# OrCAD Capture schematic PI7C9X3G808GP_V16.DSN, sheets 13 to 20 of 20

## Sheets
13 14_SIGNAL SWITCH: size Custom; note: 14_SIGNAL SWITCH
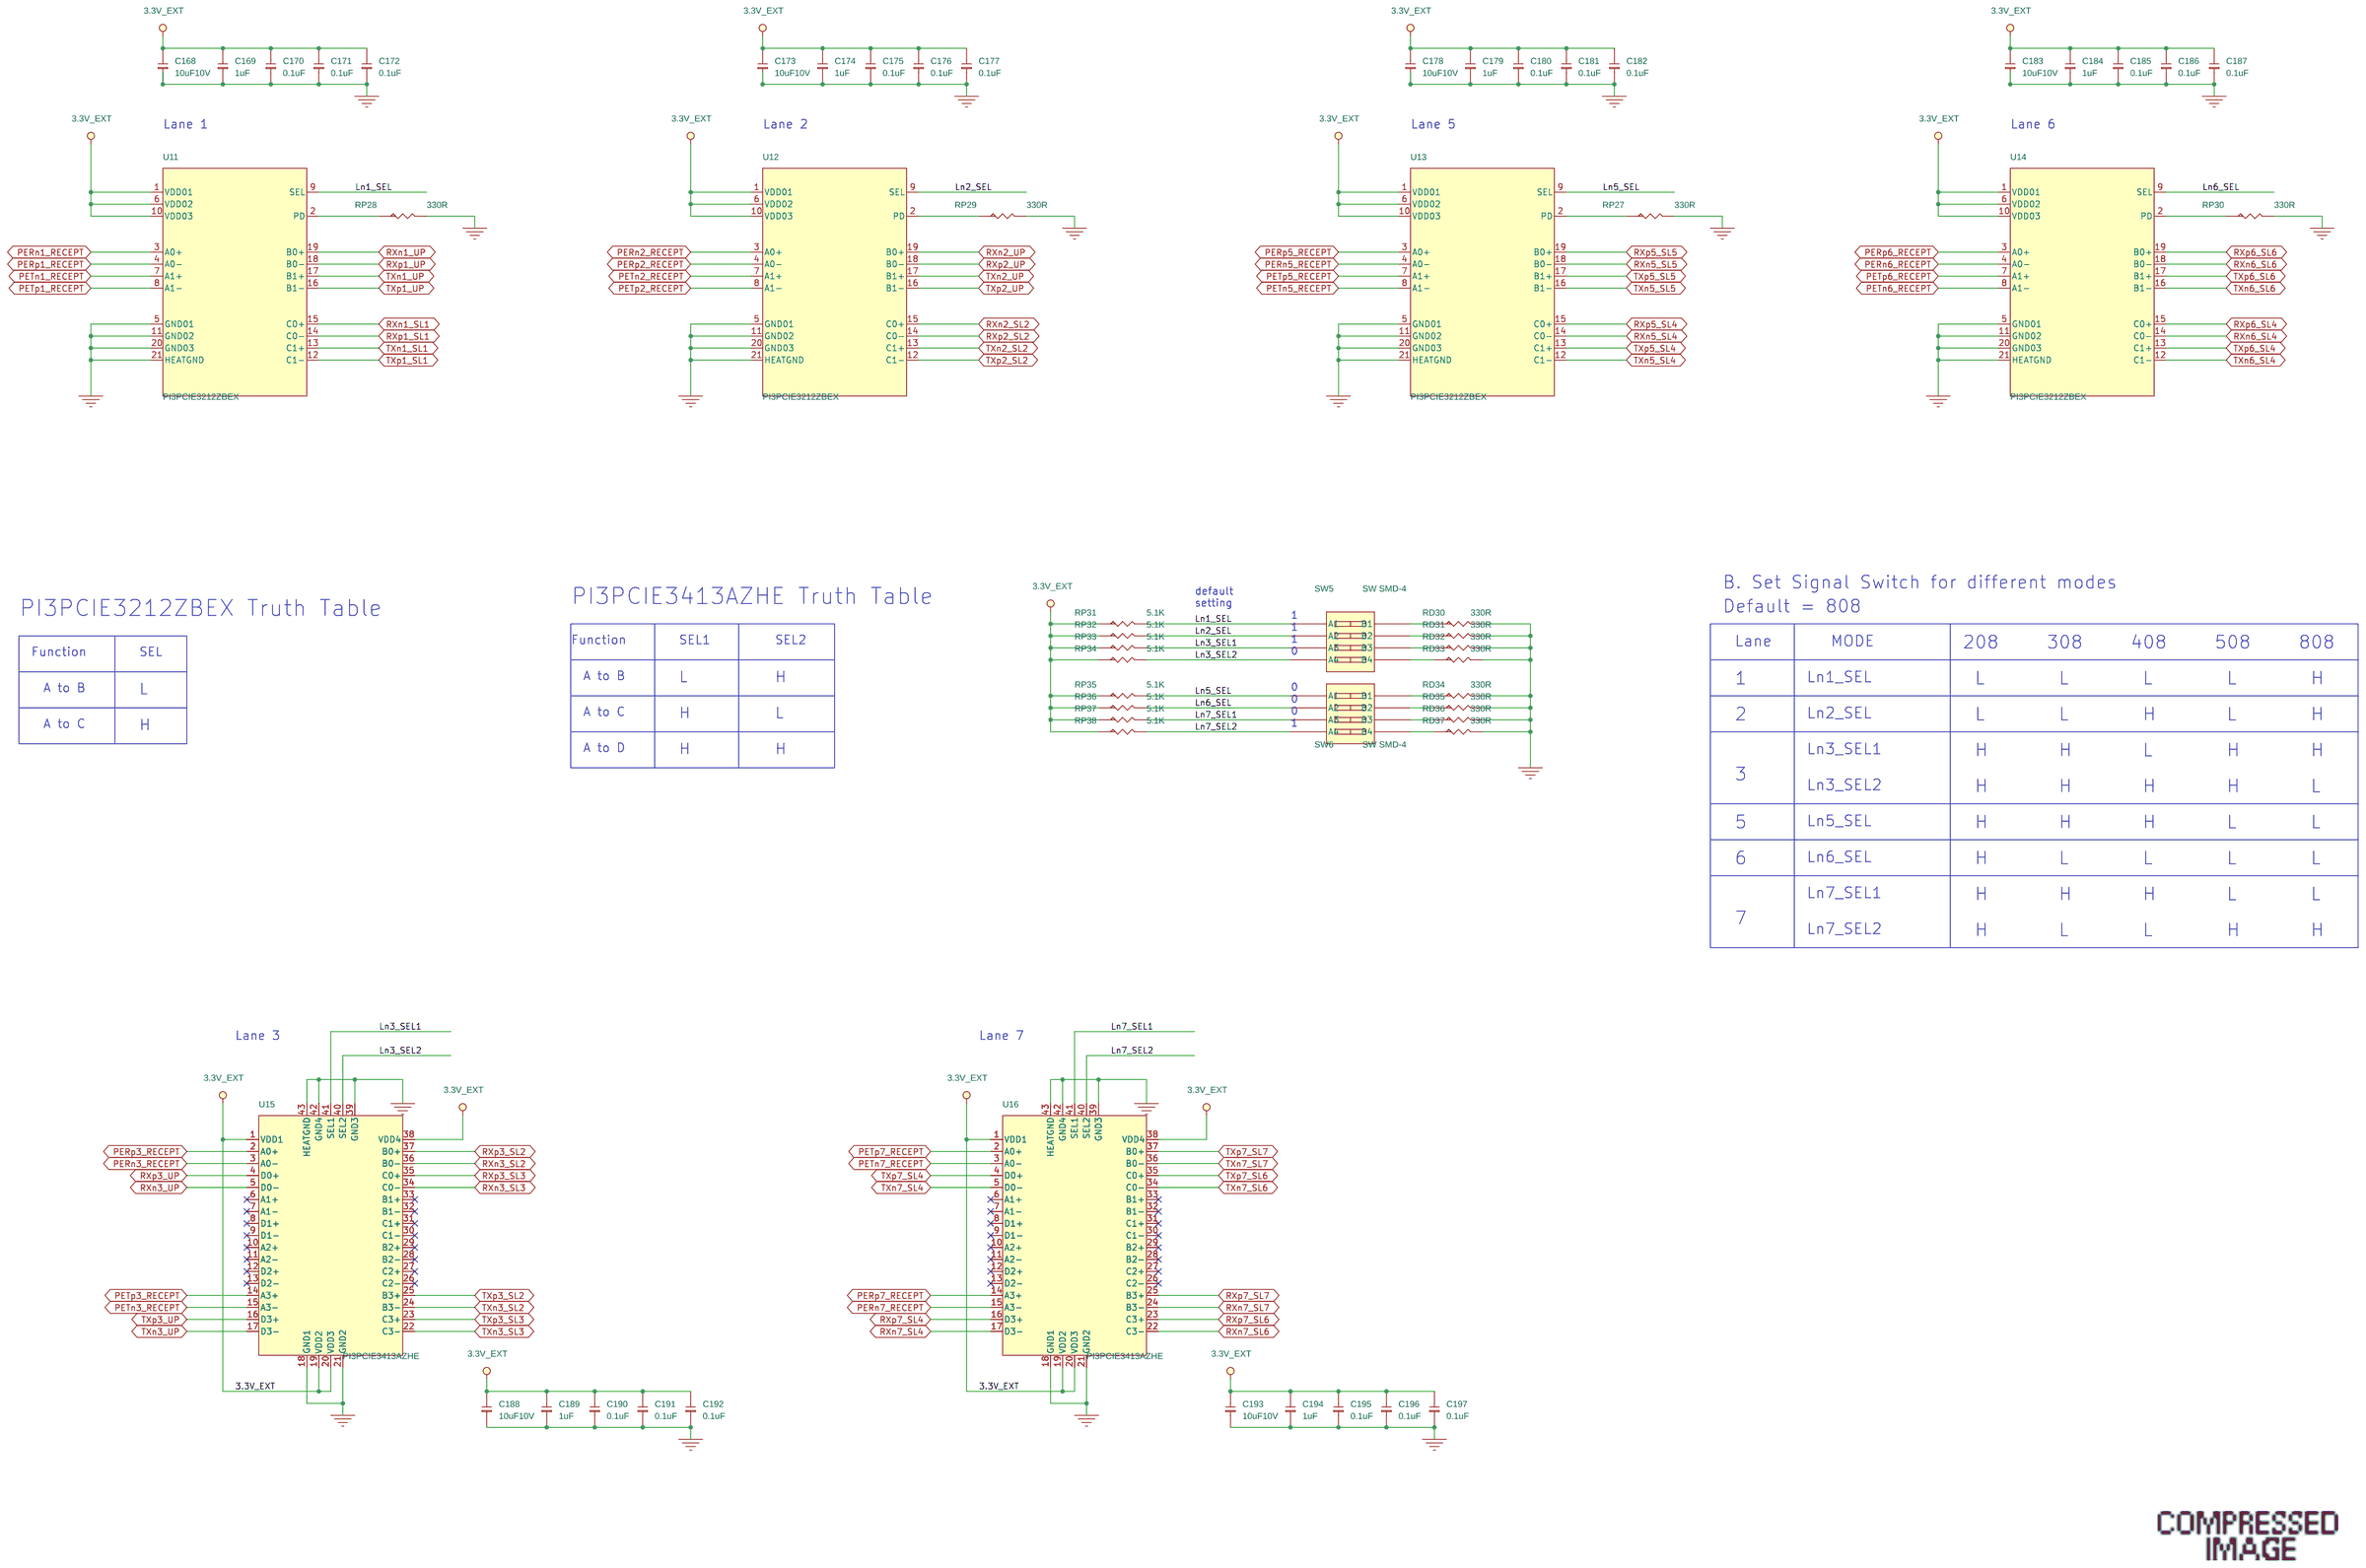
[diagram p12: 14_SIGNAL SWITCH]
14 15_CLOCK BUFFER: size B; note: 15_CLOCK BUFFER
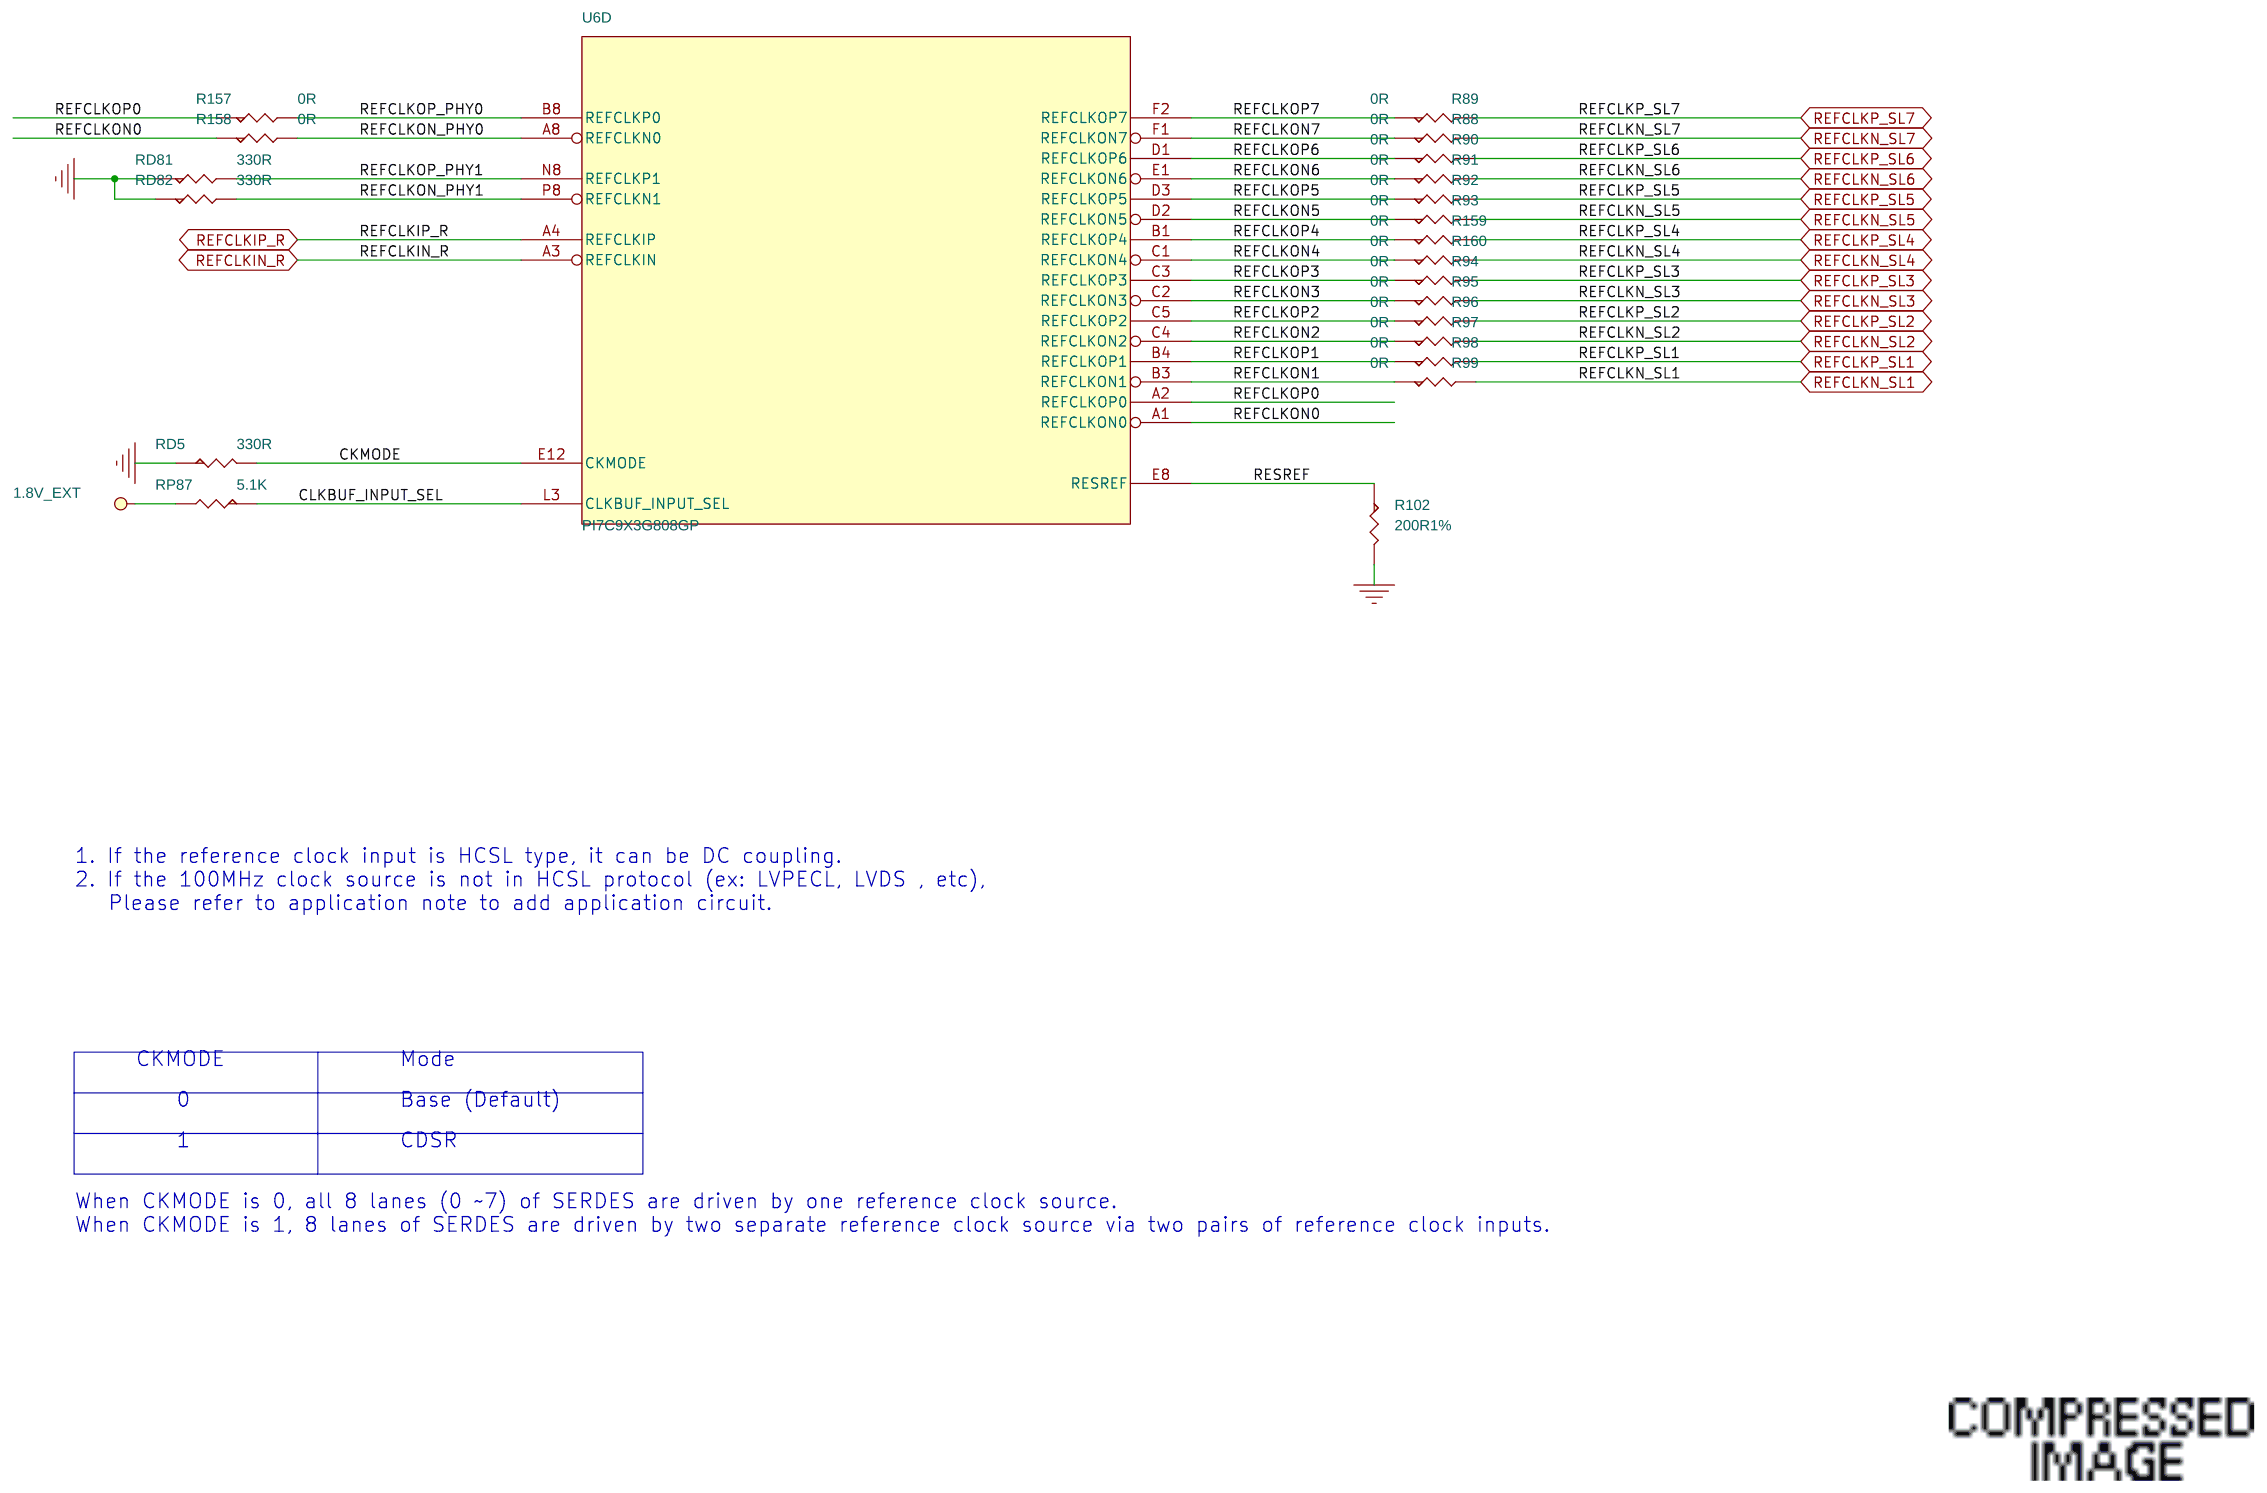
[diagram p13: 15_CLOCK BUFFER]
15 17_PERST SIGNAL: size B; note: 17_PERST SIGNAL & PORT LED
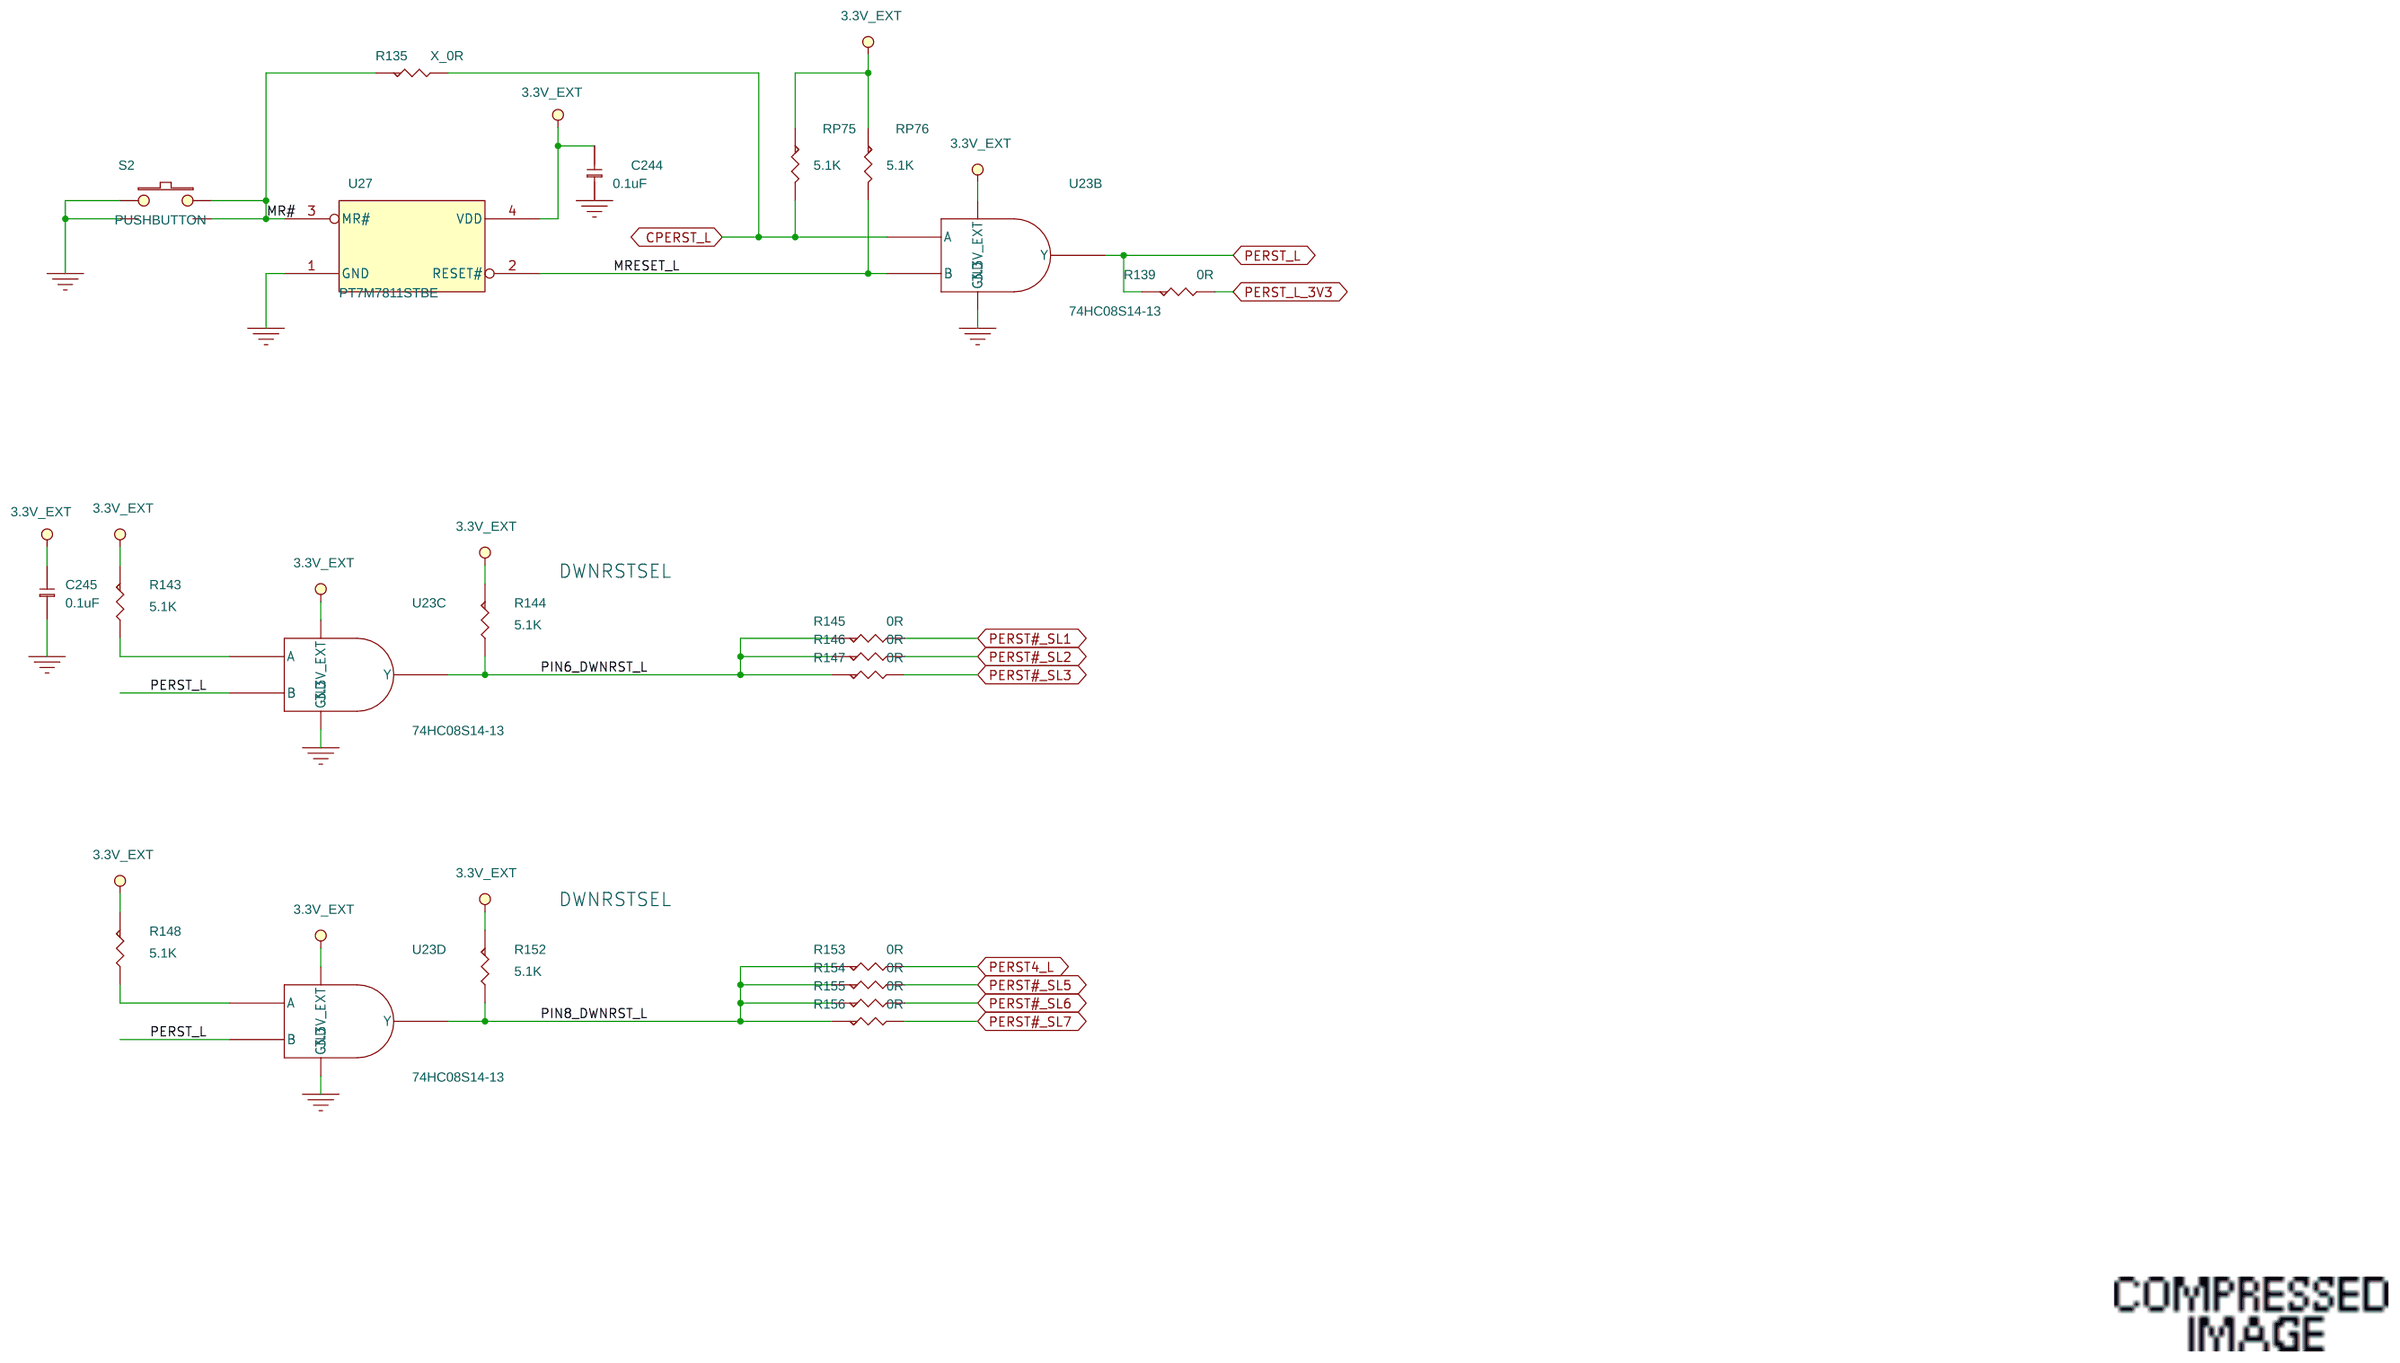
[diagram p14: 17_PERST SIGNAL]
16 18_GPIO: size B; note: 18_GPIO
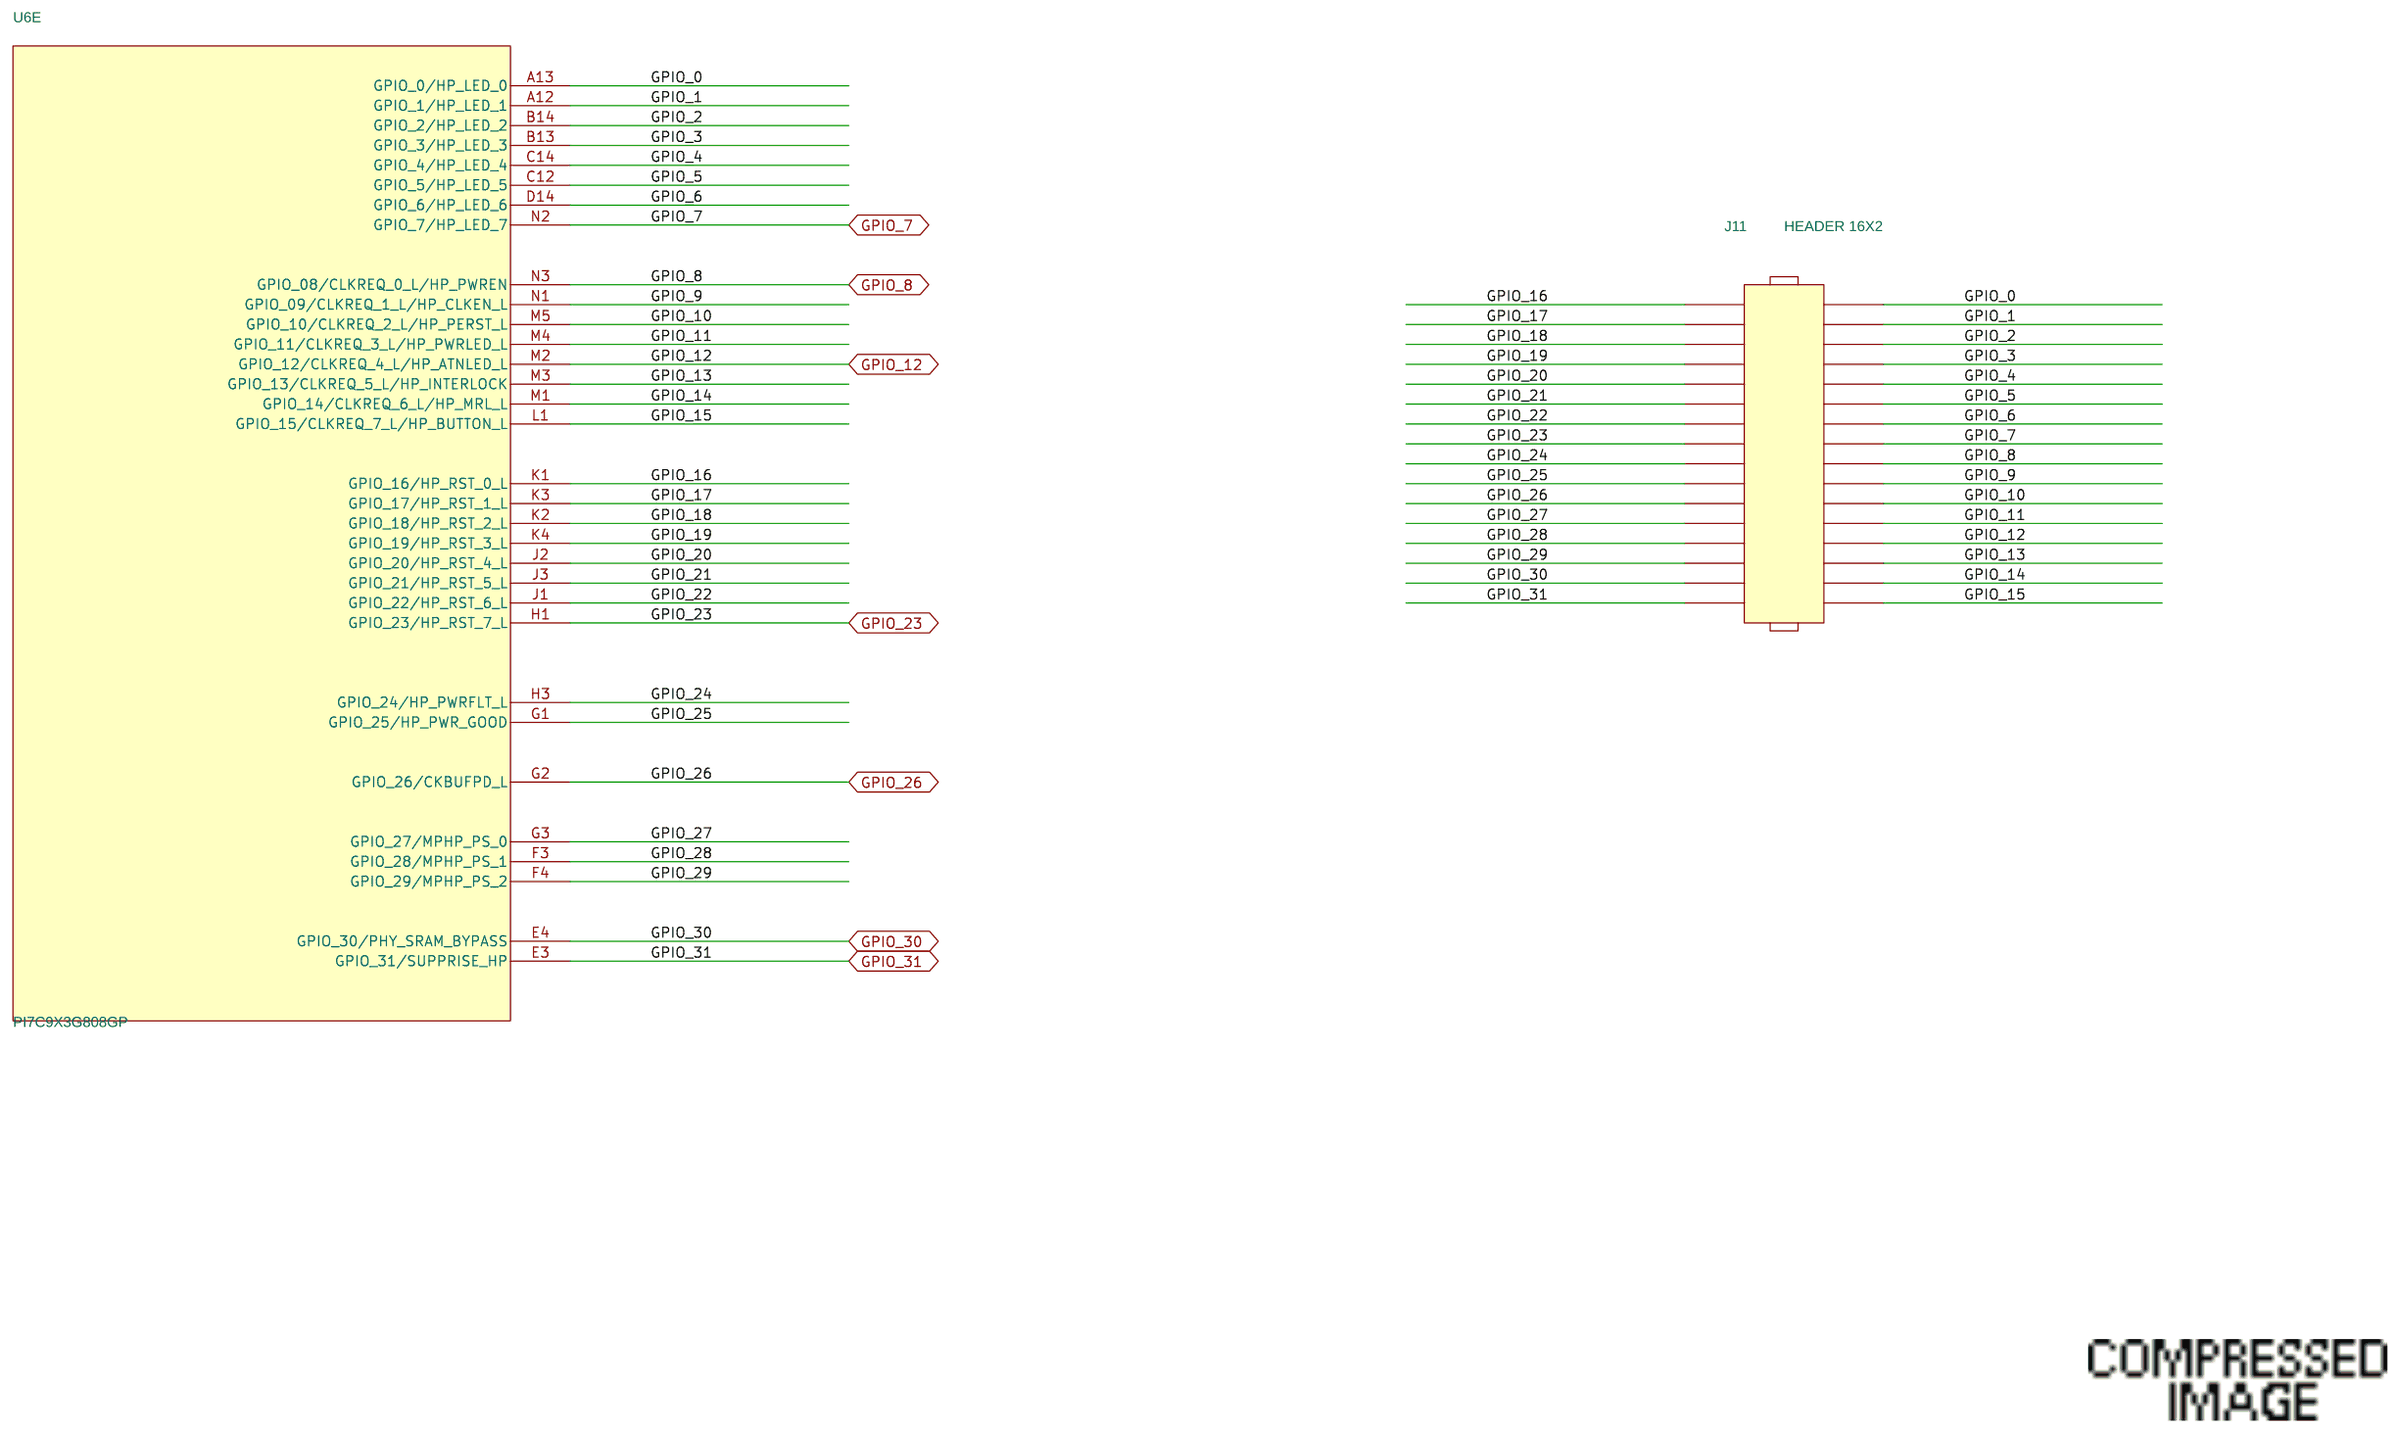
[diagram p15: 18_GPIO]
17 19_REVISION HISTORY: note: 19_REVISION HISTORY
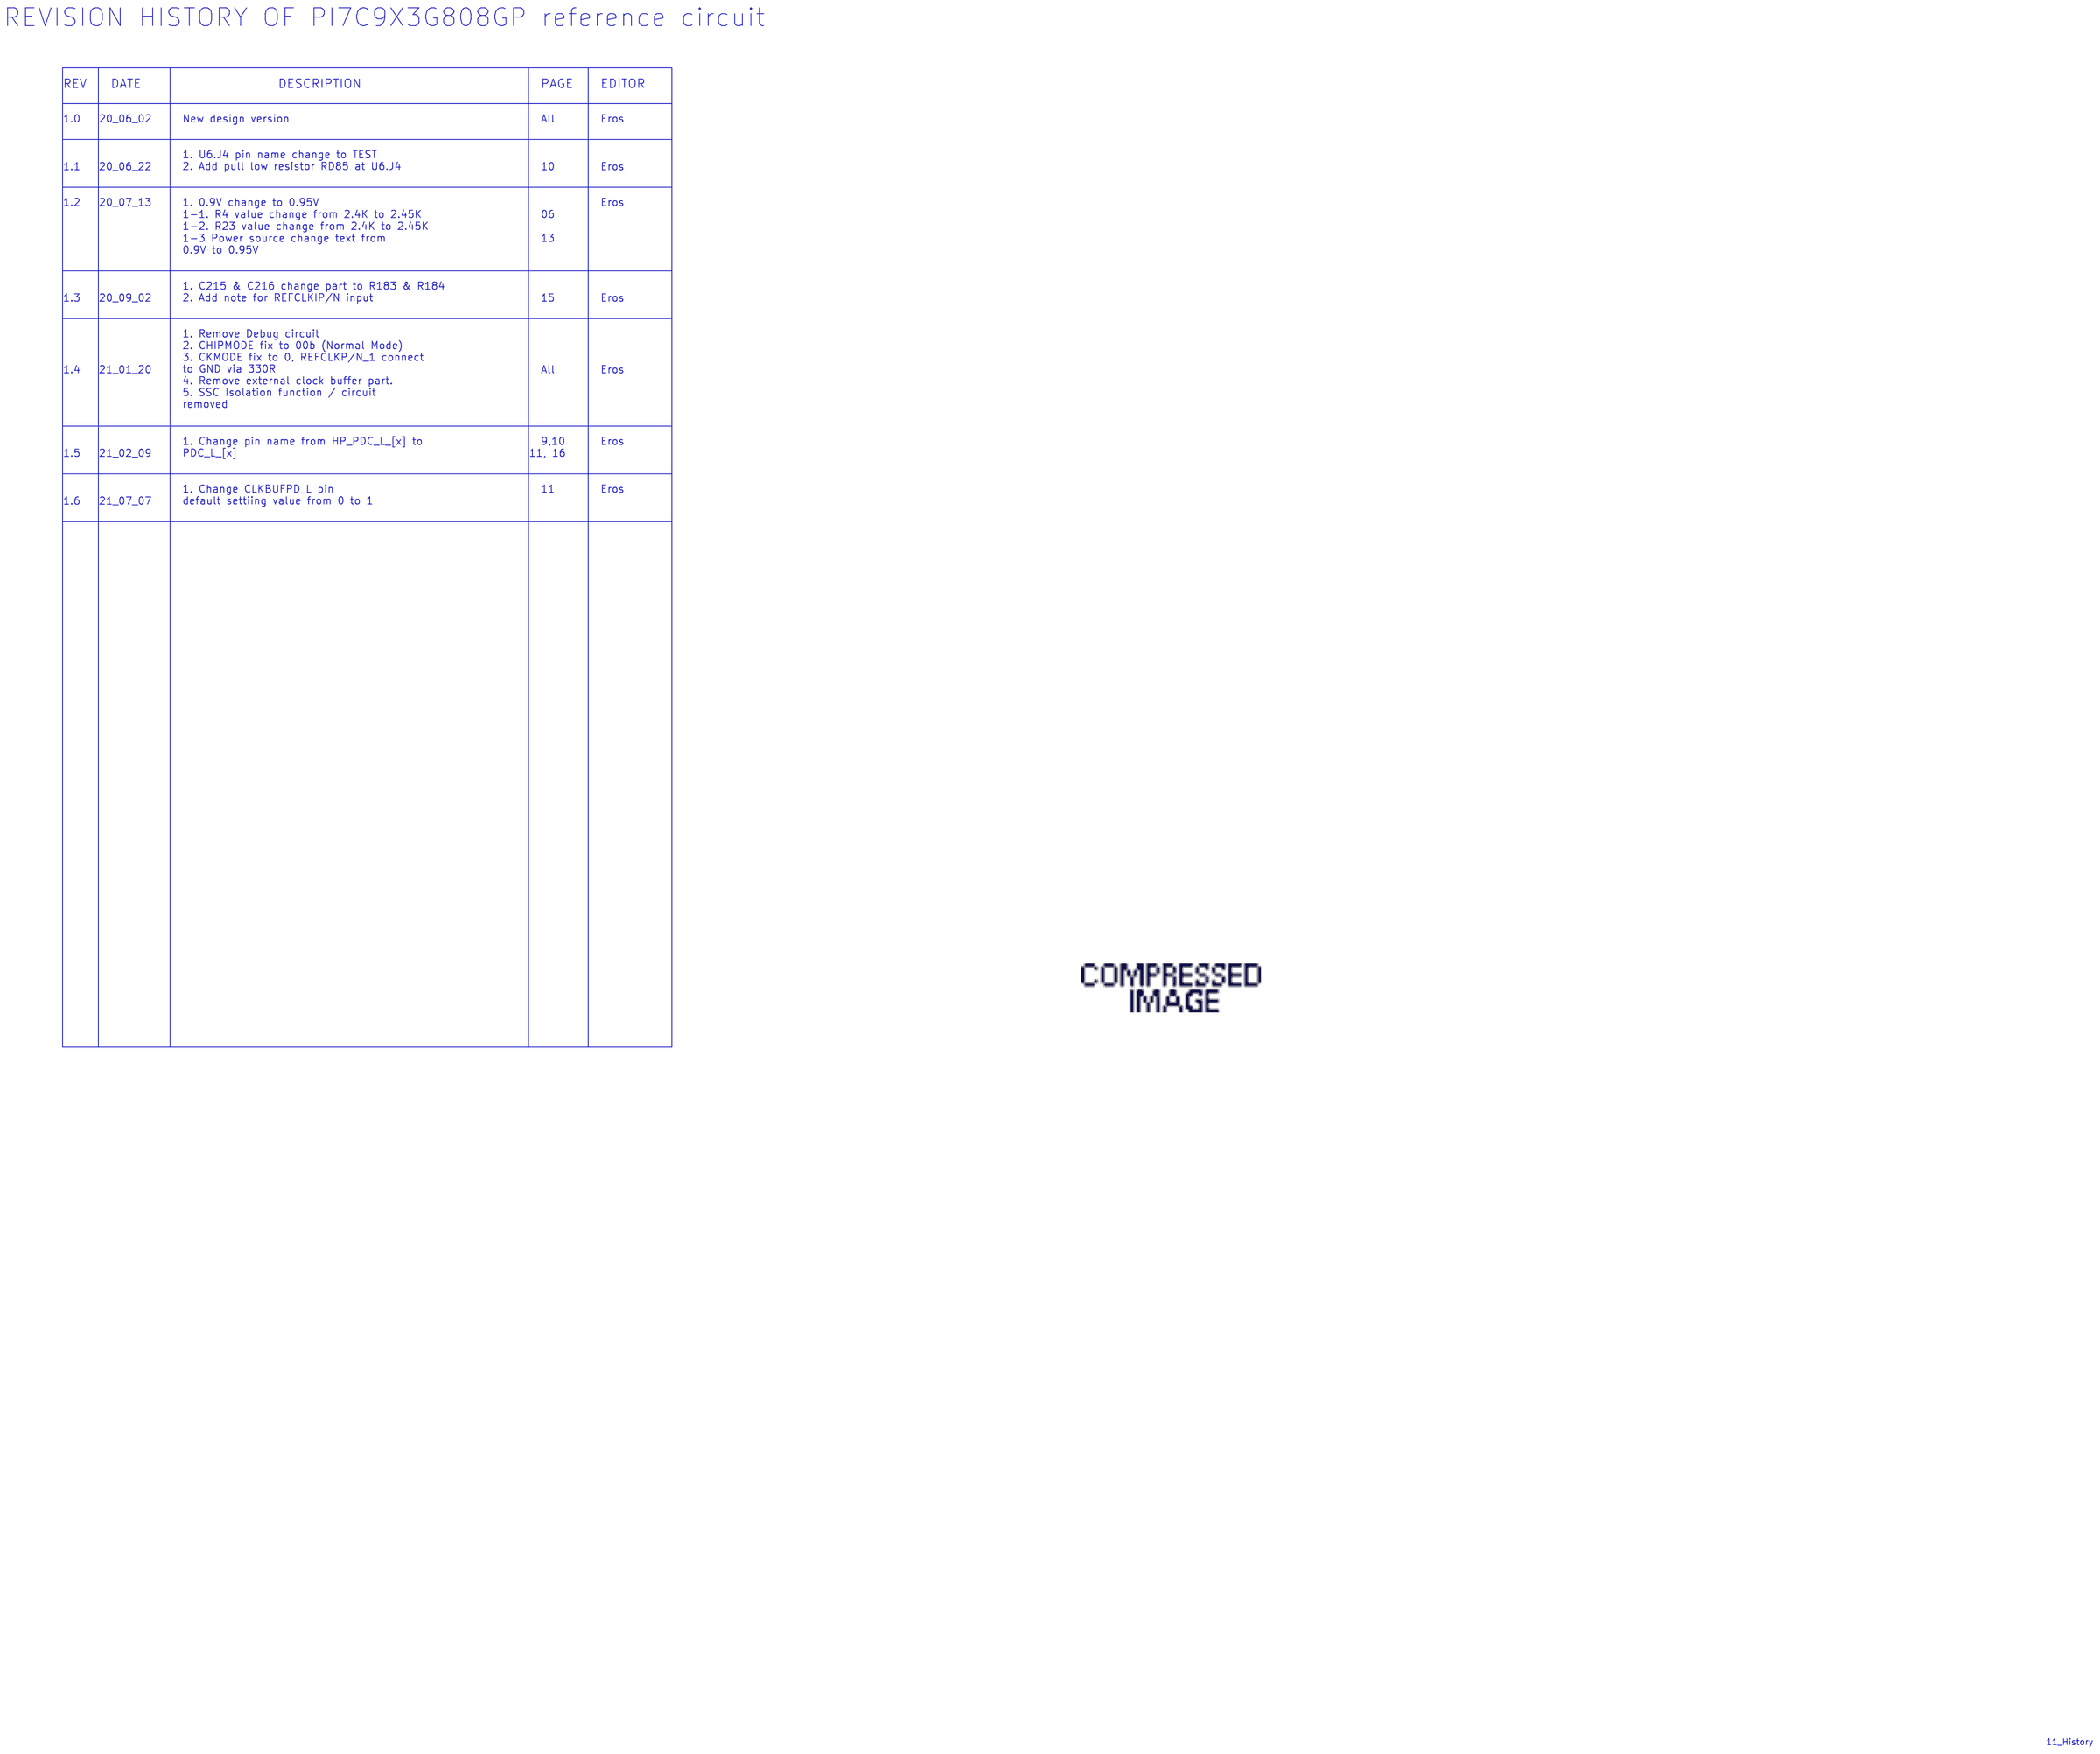
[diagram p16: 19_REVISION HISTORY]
18 20_DISCLAIMER: note: 20_DISCLAIMER
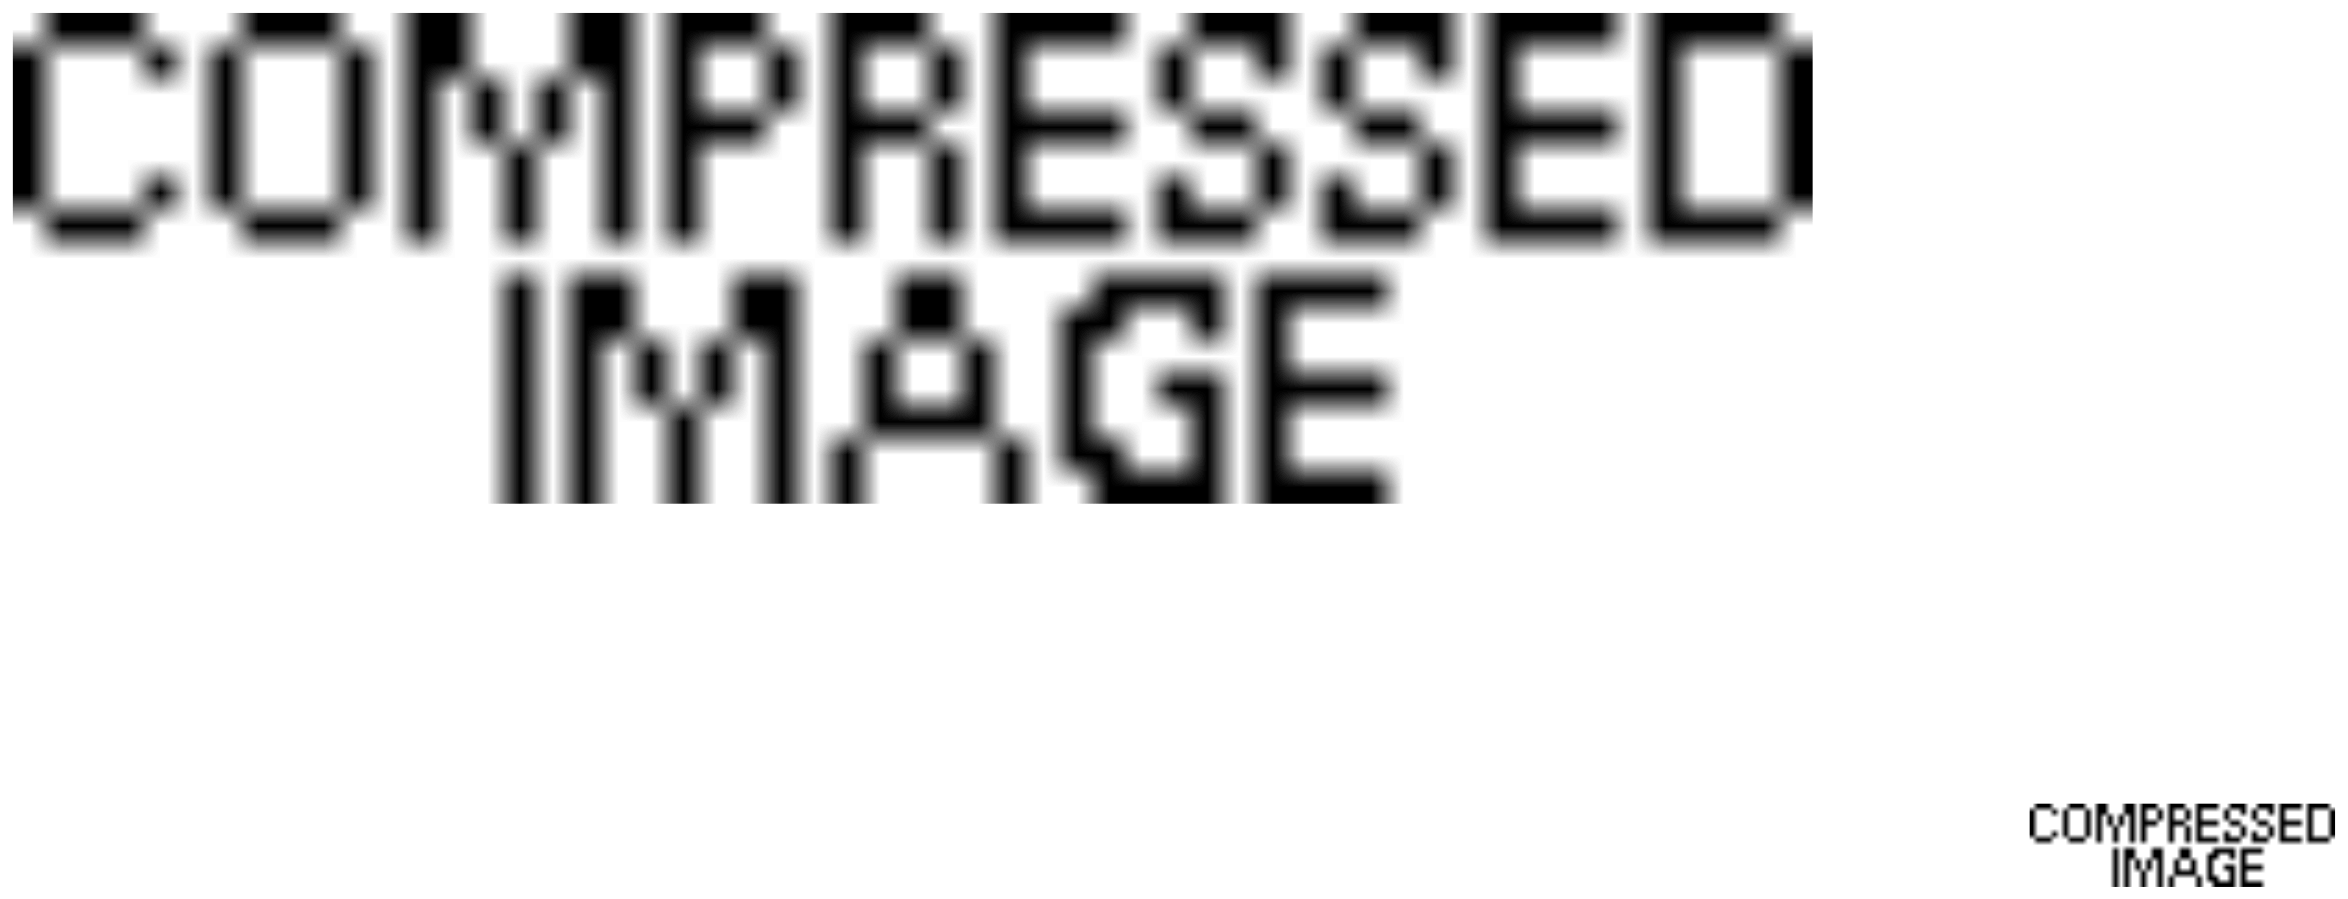
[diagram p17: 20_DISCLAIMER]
19 16_SHP / PARTIAL HP / PM L1.1: size Custom; note: 16_SHP / PARTIAL HP / PM L1.1
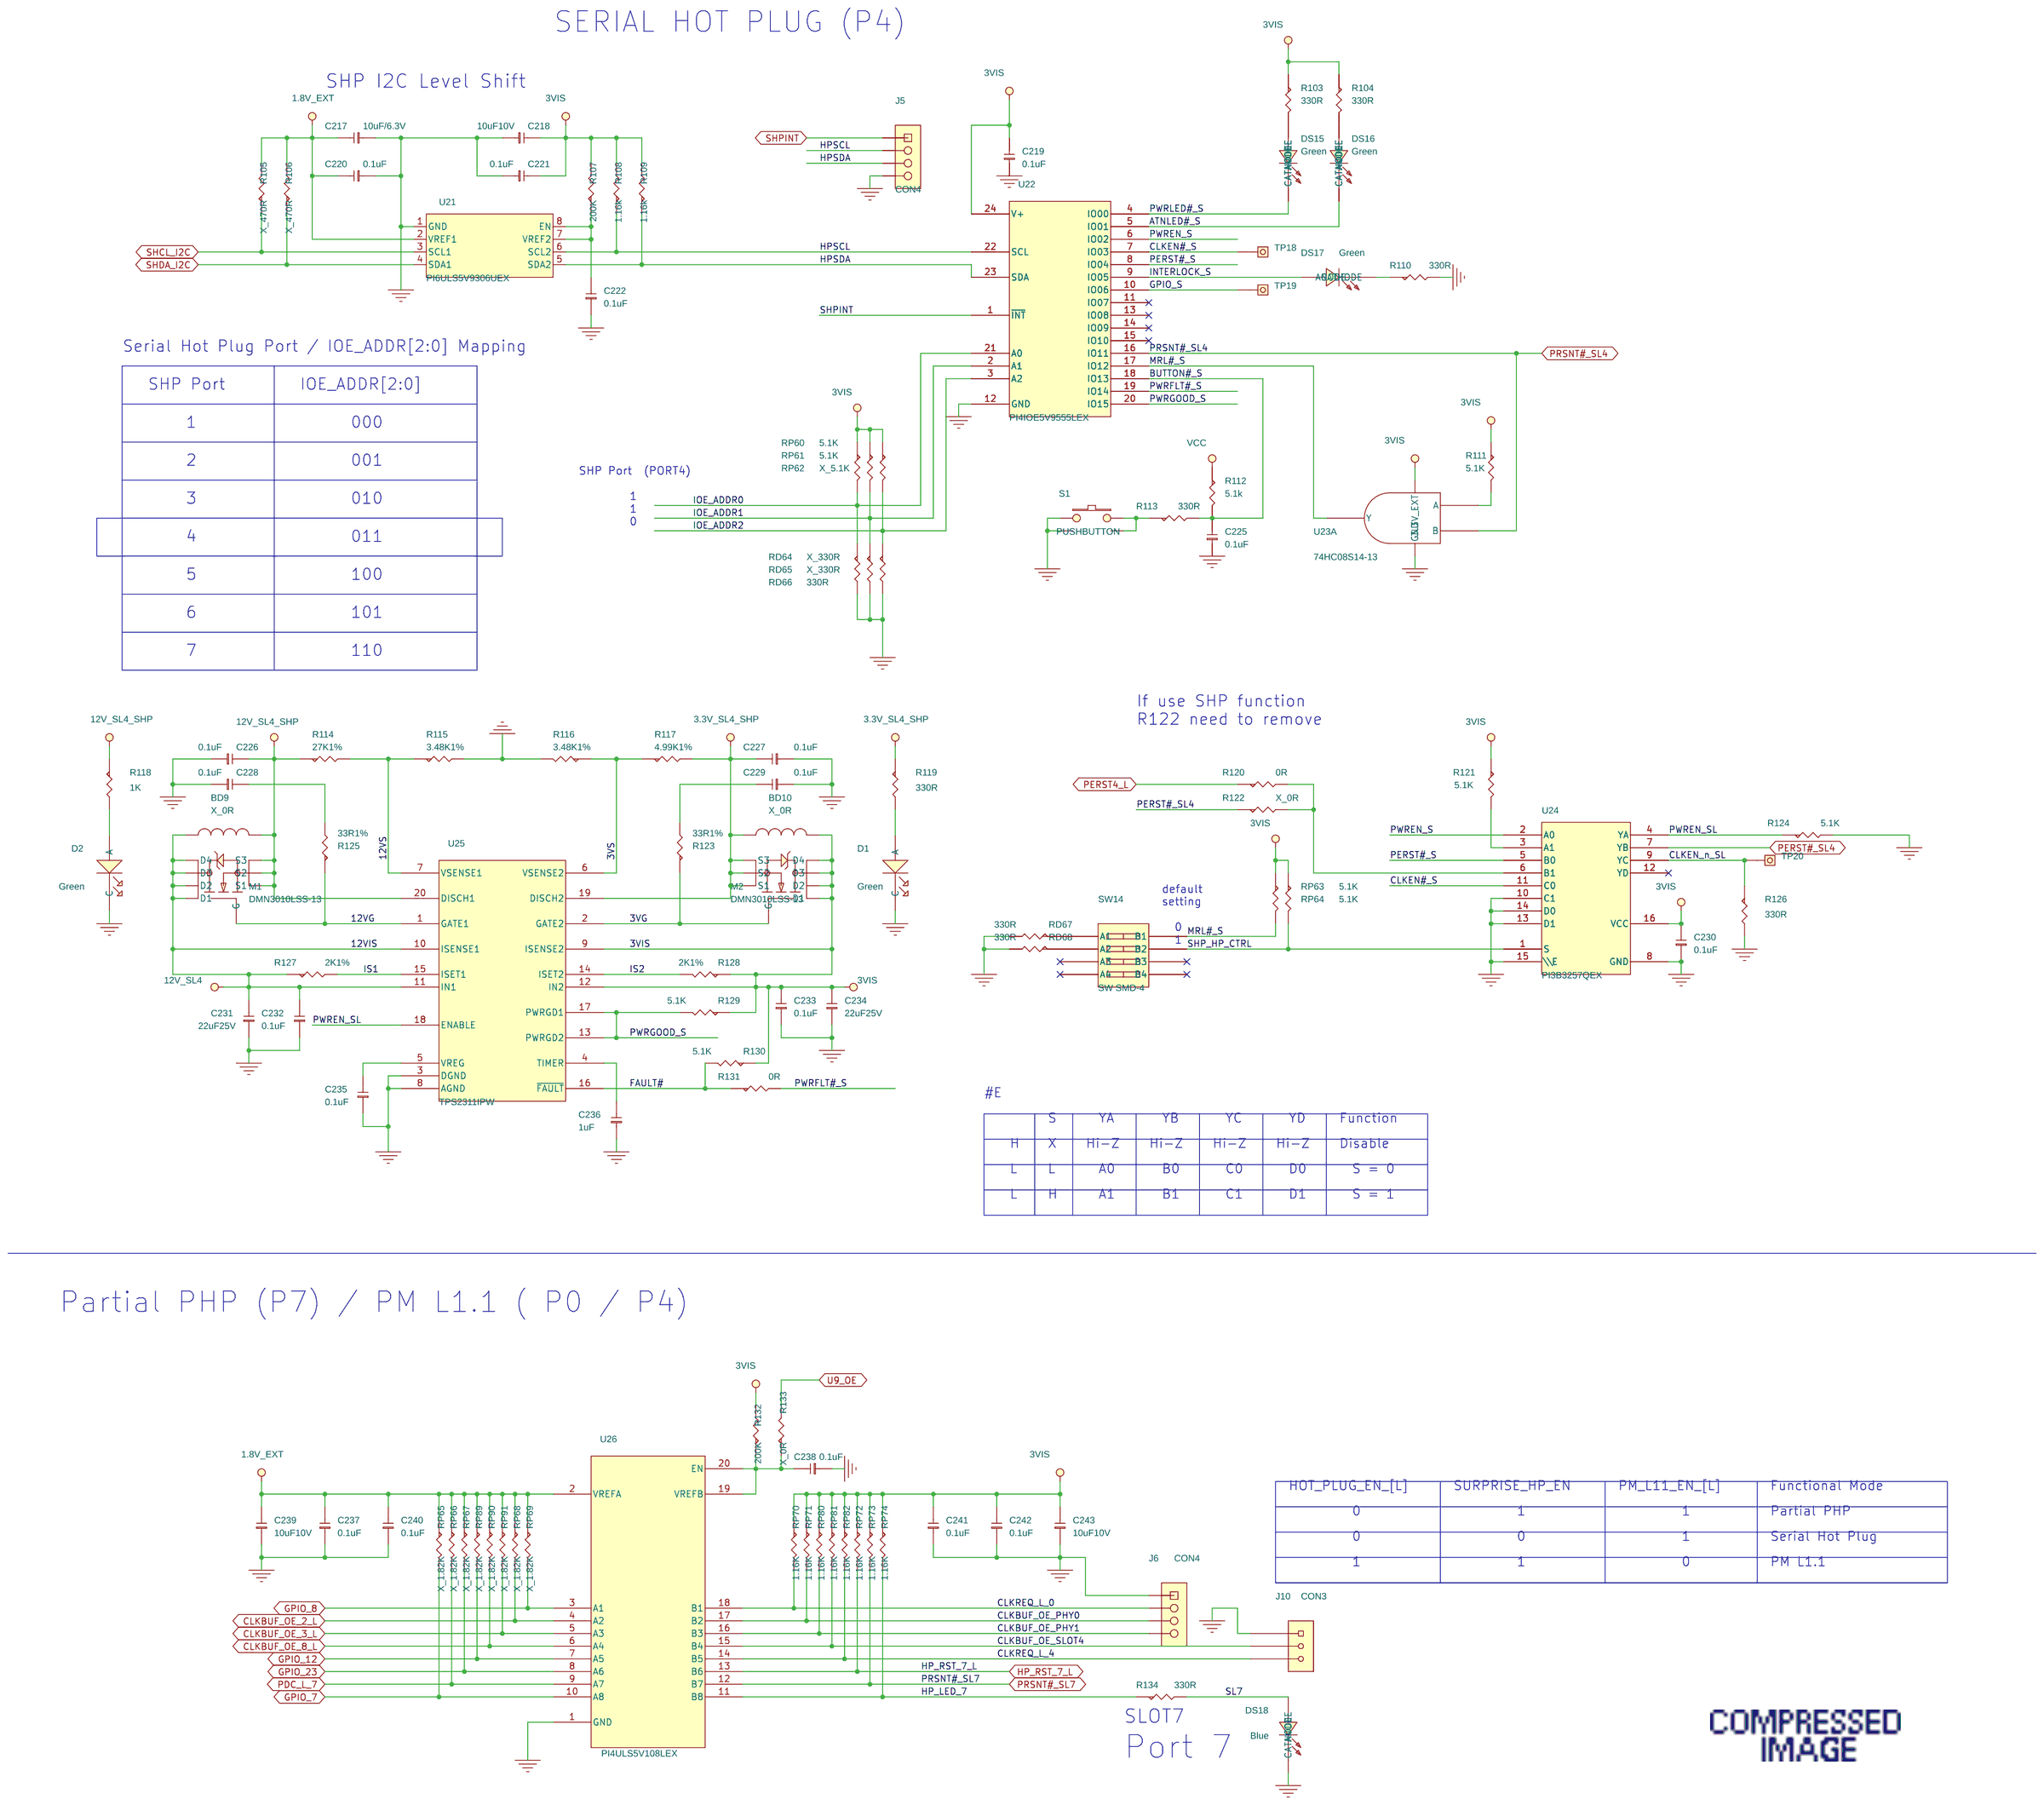
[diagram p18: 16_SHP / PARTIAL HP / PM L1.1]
20 06_ATX/3.3V_EXT/0.95VDDC_0.95VP: size Custom; note: 06_ATX/3.3V_EXT/0.95VDDC_0.95VP
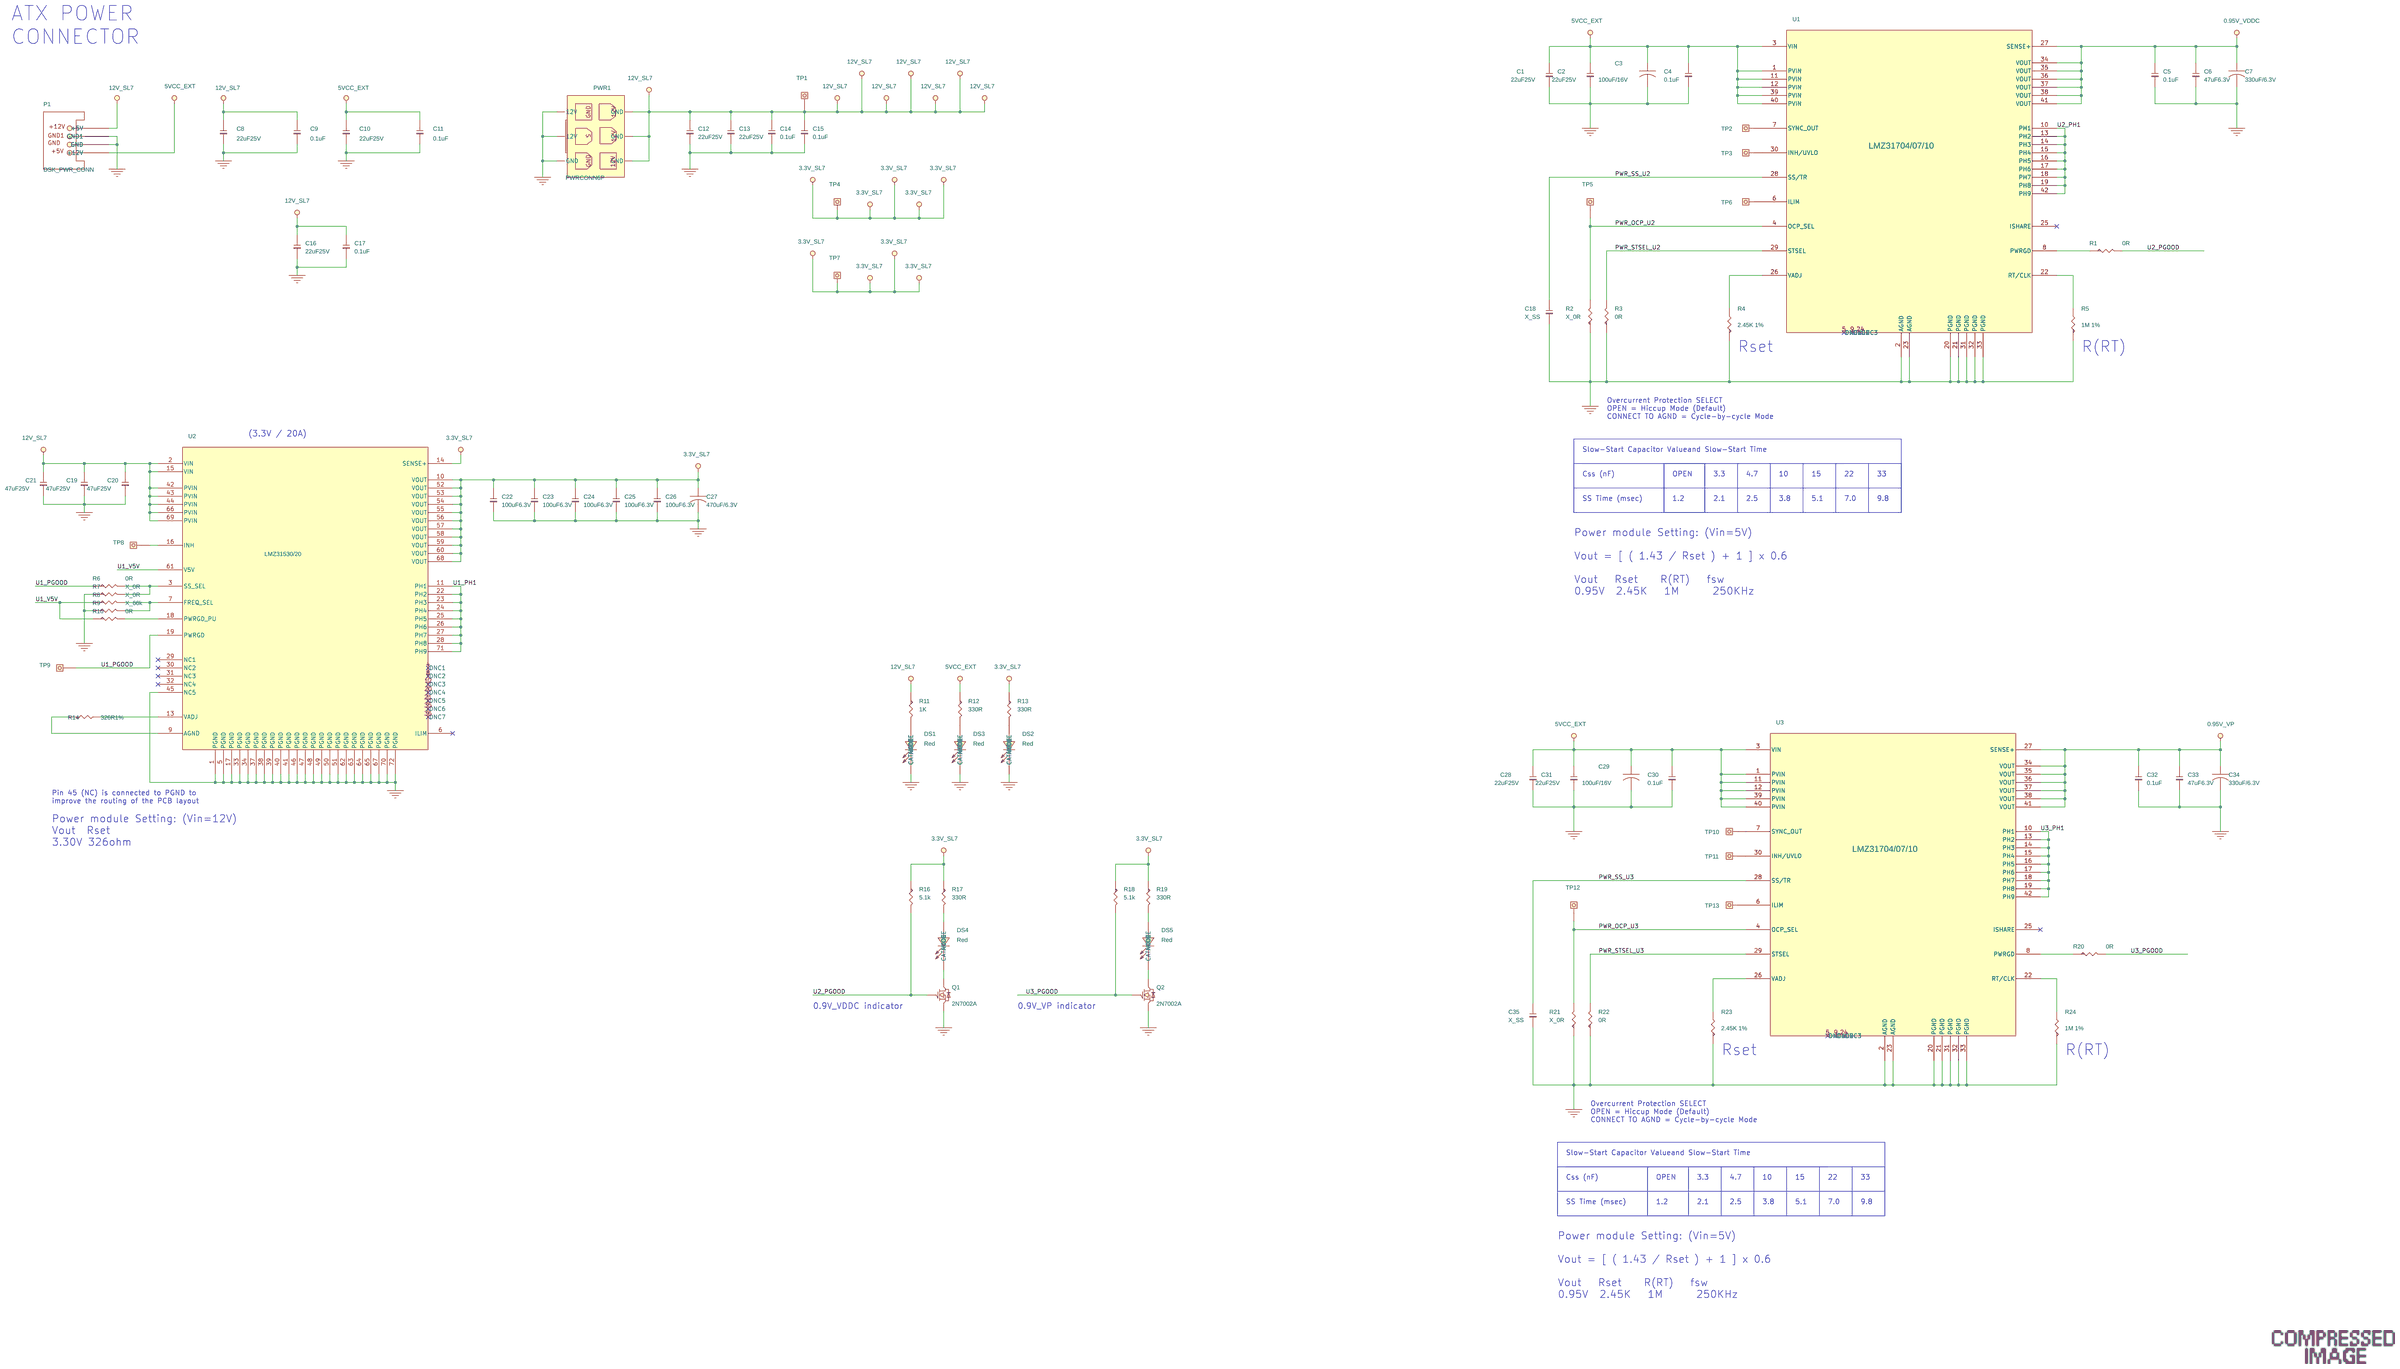
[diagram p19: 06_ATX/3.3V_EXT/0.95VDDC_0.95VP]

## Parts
sheet 06_ATX/3.3V_EXT/0.95VDDC_0.95VP
C1  22uF25V  [C1206]
C2  22uF25V  [C1206]
C3  100uF/16V  [7_3X4_3X2_8]
C4  0.1uF  [C0402]
C5  0.1uF  [C0402]
C6  47uF6.3V  [C0805]
C7  330uF/6.3V  [7_3X4_3X2_8]
C8  22uF25V  [C1206]
C9  0.1uF  [C0402]
C10  22uF25V  [C1206]
C11  0.1uF  [C0402]
C12  22uF25V  [C1206]
C13  22uF25V  [C1206]
C14  0.1uF  [C0402]
C15  0.1uF  [C0402]
C16  22uF25V  [C1206]
C17  0.1uF  [C0402]
C18  X_SS  [C0402]
C19  47uF25V  [C1206]
C20  47uF25V  [C1206]
C21  47uF25V  [C1206]
C22  100uF6.3V  [C1206]
C23  100uF6.3V  [C1206]
C24  100uF6.3V  [C1206]
C25  100uF6.3V  [C1206]
C26  100uF6.3V  [C1206]
C27  470uF/6.3V  [7_3X4_3X2_8]
C28  22uF25V  [C1206]
C29  100uF/16V  [7_3X4_3X2_8]
C30  0.1uF  [C0402]
C31  22uF25V  [C1206]
C32  0.1uF  [C0402]
C33  47uF6.3V  [C0805]
C34  330uF/6.3V  [7_3X4_3X2_8]
C35  X_SS  [C0402]
DS1  Red  [LED-0805]
DS2  Red  [LED-0805]
DS3  Red  [LED-0805]
DS4  Red  [LED-0805]
DS5  Red  [LED-0805]
P1  DSK_PWR_CONN  [PWR-4P-90]
PWR1  PWRCONN6P  [455580003]
Q1  2N7002A  [SOT23SGD_T]
Q2  2N7002A  [SOT23SGD_T]
R1  0R  [R0402]
R2  X_0R  [R0402]
R3  0R  [R0402]
R4  2.45K 1%  [R0402]
R5  1M 1%  [R0402]
R6  0R  [R0402]
R7  X_0R  [R0402]
R8  X_0R  [R0402]
R9  X_66k  [R0402]
R10  0R  [R0402]
R11  1K  [R0402]
R12  330R  [R0402]
R13  330R  [R0402]
R14  326R1%  [R0402]
R16  5.1k  [R0402]
R17  330R  [R0402]
R18  5.1k  [R0402]
R19  330R  [R0402]
R20  0R  [R0402]
R21  X_0R  [R0402]
R22  0R  [R0402]
R23  2.45K 1%  [R0402]
R24  1M 1%  [R0402]
TP1  X_TESTPOINT  [TESTPIN25]
TP2  X_TESTPOINT  [TESTPIN25]
TP3  X_TESTPOINT  [TESTPIN25]
TP4  X_TESTPOINT  [TESTPIN25]
TP5  X_TESTPOINT  [TESTPIN25]
TP6  X_TESTPOINT  [TESTPIN25]
TP7  X_TESTPOINT  [TESTPIN25]
TP8  X_TESTPOINT  [TESTPIN25]
TP9  X_TESTPOINT  [TESTPIN25]
TP10  X_TESTPOINT  [TESTPIN25]
TP11  X_TESTPOINT  [TESTPIN25]
TP12  X_TESTPOINT  [TESTPIN25]
TP13  X_TESTPOINT  [TESTPIN25]
U1  LMZ31704/07/10  [B3QFN-42]
U2  LMZ31530/20  [QFN72-16R15X15R15-_8]
U3  LMZ31704/07/10  [B3QFN-42]
sheet 14_SIGNAL SWITCH
C168  10uF10V  [C0603]
C169  1uF  [C0402]
C170  0.1uF  [C0402]
C171  0.1uF  [C0402]
C172  0.1uF  [C0402]
C173  10uF10V  [C0603]
C174  1uF  [C0402]
C175  0.1uF  [C0402]
C176  0.1uF  [C0402]
C177  0.1uF  [C0402]
C178  10uF10V  [C0603]
C179  1uF  [C0402]
C180  0.1uF  [C0402]
C181  0.1uF  [C0402]
C182  0.1uF  [C0402]
C183  10uF10V  [C0603]
C184  1uF  [C0402]
C185  0.1uF  [C0402]
C186  0.1uF  [C0402]
C187  0.1uF  [C0402]
C188  10uF10V  [C0603]
C189  1uF  [C0402]
C190  0.1uF  [C0402]
C191  0.1uF  [C0402]
C192  0.1uF  [C0402]
C193  10uF10V  [C0603]
C194  1uF  [C0402]
C195  0.1uF  [C0402]
C196  0.1uF  [C0402]
C197  0.1uF  [C0402]
RD30  330R  [R0402]
RD31  330R  [R0402]
RD32  330R  [R0402]
RD33  330R  [R0402]
RD34  330R  [R0402]
RD35  330R  [R0402]
RD36  330R  [R0402]
RD37  330R  [R0402]
RP27  330R  [R0402]
RP28  330R  [R0402]
RP29  330R  [R0402]
RP30  330R  [R0402]
RP31  5.1K  [R0402]
RP32  5.1K  [R0402]
RP33  5.1K  [R0402]
RP34  5.1K  [R0402]
RP35  5.1K  [R0402]
RP36  5.1K  [R0402]
RP37  5.1K  [R0402]
RP38  5.1K  [R0402]
SW5  SW SMD-4  [CT2184LPST]
SW6  SW SMD-4  [CT2184LPST]
U11  PI3PCIE3212ZBEX  [TQFN20]
U12  PI3PCIE3212ZBEX  [TQFN20]
U13  PI3PCIE3212ZBEX  [TQFN20]
U14  PI3PCIE3212ZBEX  [TQFN20]
U15  PI3PCIE3413AZHE  [TQFN42]
U16  PI3PCIE3413AZHE  [TQFN42]
sheet 15_CLOCK BUFFER
R88  0R  [R0402]
R89  0R  [R0402]
R90  0R  [R0402]
R91  0R  [R0402]
R92  0R  [R0402]
R93  0R  [R0402]
R94  0R  [R0402]
R95  0R  [R0402]
R96  0R  [R0402]
R97  0R  [R0402]
R98  0R  [R0402]
R99  0R  [R0402]
R102  200R1%  [R0402]
R157  0R  [R0402]
R158  0R  [R0402]
R159  0R  [R0402]
R160  0R  [R0402]
RD5  330R  [R0402]
RD81  330R  [R0402]
RD82  330R  [R0402]
RP87  5.1K  [R0402]
sheet 16_SHP / PARTIAL HP / PM L1.1
BD9  X_0R  [L1206]
BD10  X_0R  [L1206]
C217  10uF/6.3V  [C0402]
C218  10uF10V  [C0603]
C219  0.1uF  [C0402]
C220  0.1uF  [C0402]
C221  0.1uF  [C0402]
C222  0.1uF  [C0402]
C225  0.1uF  [C0402]
C226  0.1uF  [C0402]
C227  0.1uF  [C0402]
C228  0.1uF  [C0402]
C229  0.1uF  [C0402]
C230  0.1uF  [C0402]
C231  22uF25V  [C1206]
C232  0.1uF  [C0402]
C233  0.1uF  [C0402]
C234  22uF25V  [C1206]
C235  0.1uF  [C0402]
C236  1uF  [C0402]
C237  0.1uF  [C0402]
C238  0.1uF  [C0402]
C239  10uF10V  [C0603]
C240  0.1uF  [C0402]
C241  0.1uF  [C0402]
C242  0.1uF  [C0402]
C243  10uF10V  [C0603]
D1  Green  [LED-0805]
D2  Green  [LED-0805]
DS15  Green  [LED-0805]
DS16  Green  [LED-0805]
DS17  Green  [LED-0805]
DS18  Blue  [LED-0805]
J5  CON4  [HEAD1X4_2_54MM]
J6  CON4  [HEAD1X4_2_54MM]
J10  CON3  [HEAD1X3_2_54MM]
M1  DMN3010LSS-13  [SO8-6-1_27]
M2  DMN3010LSS-13  [SO8-6-1_27]
R103  330R  [R0402]
R104  330R  [R0402]
R105  X_470R  [R0402]
R106  X_470R  [R0402]
R107  200K  [R0402]
R108  1.16k  [R0402]
R109  1.16k  [R0402]
R110  330R  [R0402]
R111  5.1K  [R0402]
R112  5.1k  [R0402]
R113  330R  [R0402]
R114  27K1%  [R0402]
R115  3.48K1%  [R0402]
R116  3.48K1%  [R0402]
R117  4.99K1%  [R0402]
R118  1K  [R0402]
R119  330R  [R0402]
R120  0R  [R0402]
R121  5.1K  [R0402]
R122  X_0R  [R0402]
R123  33R1%  [R0402]
R124  5.1K  [R0402]
R125  33R1%  [R0402]
R126  330R  [R0402]
R127  2K1%  [R0402]
R128  2K1%  [R0402]
R129  5.1K  [R0402]
R130  5.1K  [R0402]
R131  0R  [R0402]
R132  200K  [R0402]
R133  X_0R  [R0402]
R134  330R  [R0402]
RD64  X_330R  [R0402]
RD65  X_330R  [R0402]
RD66  330R  [R0402]
RD67  330R  [R0402]
RD68  330R  [R0402]
RP60  5.1K  [R0402]
RP61  5.1K  [R0402]
RP62  X_5.1K  [R0402]
RP63  5.1K  [R0402]
RP64  5.1K  [R0402]
RP65  X_1.82K  [R0402]
RP66  X_1.82K  [R0402]
RP67  X_1.82K  [R0402]
RP68  X_1.82K  [R0402]
RP69  X_1.82K  [R0402]
RP70  1.16K  [R0402]
RP71  1.16K  [R0402]
RP72  1.16K  [R0402]
RP73  1.16K  [R0402]
RP74  1.16K  [R0402]
RP80  1.16K  [R0402]
RP81  1.16K  [R0402]
RP82  1.16K  [R0402]
RP89  X_1.82K  [R0402]
RP90  X_1.82K  [R0402]
RP91  X_1.82K  [R0402]
S1  PUSHBUTTON  [SW-1102]
SW14  SW SMD-4  [CT2184LPST]
TP18  X_TESTPOINT  [TESTPIN25]
TP19  X_TESTPOINT  [TESTPIN25]
TP20  X_TESTPOINT  [TESTPIN25]
U21  PI6ULS5V9306UEX  [MSOP-8L]
U22  PI4IOE5V9555LEX  [TSSOP24-6_5-_65]
U23  74HC08S14-13  [SO14-6-1_27]  (sections A,B,C,D)
U24  PI3B3257QEX  [qsop16-6-_635]
U25  TPS2311IPW  [tssop20-6_5-_65]
U26  PI4ULS5V108LEX  [tssop20-6_5-_65]
sheet 17_PERST SIGNAL
C244  0.1uF  [C0402]
C245  0.1uF  [C0402]
R135  X_0R  [R0402]
R139  0R  [R0402]
R143  5.1K  [R0402]
R144  5.1K  [R0402]
R145  0R  [R0402]
R146  0R  [R0402]
R147  0R  [R0402]
R148  5.1K  [R0402]
R152  5.1K  [R0402]
R153  0R  [R0402]
R154  0R  [R0402]
R155  0R  [R0402]
R156  0R  [R0402]
RP75  5.1K  [R0402]
RP76  5.1K  [R0402]
S2  PUSHBUTTON  [SW-1102]
U27  PT7M7811STBE  [SOT143]
sheet 18_GPIO
J11  HEADER 16X2
U6  PI7C9X3G808GP  [HFCBGA_196_15X15]  (sections A,B,C,D,E)

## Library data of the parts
C1 C2 C4-C6 C8-C26 C28 C30-C33 C35 C168-C197 C218 C220-C222 C225 C231-C234 C237 C239-C243 = C_MLCC: CLASS: DISCRETE; Symbol Name: _
C3 C7 C27 C29 C34 = CAP_0
DS1-DS5 DS15-DS18 = LED_0
P1 = DSK_PWR_CONN_1: PCBFootprint: PWR-ATX-4; PartReference: P7
PWR1 = PWR_ATX12V_3: Remark: _; Symbol Name: _
Q1 Q2 = NMOS_SGD_0: Asm Cfg: 5010; Asm Comm: 5010; GREEN_TYPE: 1-RH§C¦Ã¬V; Remark: _; Symbol Name: _
R1-R14 R16-R24 = R_2P: Remark: _; Symbol Name: _
TP1-TP13 TP18-TP20 = TP_0
U1 U3 = LMZ31704_70_10
U2 = LM31530_20
RD5 RD30-RD37 RD64-RD68 RP27-RP38 RP60-RP76 RP80-RP82 RP89-RP91 = R_2P
SW5 SW6 SW14 = SW_SMT-4_0
U11-U14 = PI3PCIE3212ZBEX
U15 U16 = PI3PCIE3413ZHE
R88-R99 R157-R160 RD81 RD82 RP87 = R: Asm Cfg: 5010; Asm Comm: 5010; GREEN_TYPE: 7-HE µL³¿¯À&¼Ú·ù±Æ¥~±ø´Ú; Remark: _; Symbol Name: _
R102 = R_4: Asm Cfg: 5010; Asm Comm: 5010; CLASS: DISCRETE; GREEN_TYPE: 1-RH§C¦Ã¬V; Symbol Name: _
BD9 BD10 = INDUCTOR_0
C217 = C_MLCC_0: alt_symbols: (c0402,c0402_bga;b:c0402,c0402_bga)
C219 C226-C230 C235 C236 C244 C245 = C_MLCC: Symbol Name: _
C238 = C_MLCC_0: Asm Cfg: 5010; Asm Comm: 5010; CLASS: DISCRETE; GREEN_TYPE: 1-RH§C¦Ã¬V; Symbol Name: _
D1 D2 = LED_5
J5 J6 = H1X3_0: Symbol Name: _
J10 = BH1X4B-1_9: Symbol Name: _
M1 M2 = SI4884DY_0
R103 R104 R110 R112 R121 R123 R125 = R_4: Symbol Name: _; Value2: 1%
R105-R109 R111 R113-R120 R122 R124 R126-R135 R139 R143-R148 R152-R156 = R_2P: Symbol Name: _
S1 S2 = SWITCH_0
U21 = W25QXX_3
U22 = MAX7311
U23 = 74HC08_6
U24 = PI3B3257_1
U25 = TPS2311_0
U26 = PI4ULS5V108LEX
U27 = TCM811_1
J11 = HEADER_16X2
U6 = PI7C9X3G808GP_17

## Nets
0.95V_VDDC: C5.2 C6.2 C7.1 U1.27(SENSE+) U1.34(VOUT) U1.35(VOUT) U1.36(VOUT) U1.37(VOUT) U1.38(VOUT) U1.41(VOUT) ; also on sheet 12
0.95V_VP: C32.2 C33.2 C34.1 U3.27(SENSE+) U3.34(VOUT) U3.35(VOUT) U3.36(VOUT) U3.37(VOUT) U3.38(VOUT) U3.41(VOUT) ; also on sheet 12
1.8V_EXT: C217.2 C220.2 C237.2 C239.2 C240.2 R105.2 R106.2 RP65.1 RP66.1 RP67.1 RP68.1 RP69.1 RP87.2 RP89.1 RP90.1 RP91.1 U21.2(VREF1) U26.2(VREFA) ; also on sheet 1 8 9 10 12
3.3V_EXT: BD10.2 C22.2 C23.2 C24.2 C25.2 C26.2 C27.1 C168.2 C169.2 C170.2 C171.2 C172.2 C173.2 C174.2 C175.2 C176.2 C177.2 C178.2 C179.2 C180.2 C181.2 C182.2 C183.2 C184.2 C185.2 C186.2 C187.2 C188.2 C189.2 C190.2 C191.2 C192.2 C193.2 C194.2 C195.2 C196.2 C197.2 C218.2 C219.2 C221.2 C230.2 C233.2 C234.2 C241.2 C242.2 C243.2 C244.2 C245.2 M2.5(D1) M2.6(D2) M2.7(D3) M2.8(D4) R13.1 R16.1 R17.1 R18.1 R19.1 R103.1 R104.1 R107.2 R108.2 R109.2 R111.1 R112.1 R121.1 R128.1 R129.1 R130.1 R132.2 R143.1 R144.1 R148.1 R152.1 RP31.1 RP32.1 RP33.1 RP34.1 RP35.1 RP36.1 RP37.1 RP38.1 RP60.1 RP61.1 RP62.1 RP63.1 RP64.1 RP70.1 RP71.1 RP72.1 RP73.1 RP74.1 RP75.1 RP76.1 RP80.1 RP81.1 RP82.1 TP4.1 TP7.1 U2.10(VOUT) U2.14(SENSE+) U2.52(VOUT) U2.53(VOUT) U2.54(VOUT) U2.55(VOUT) U2.56(VOUT) U2.57(VOUT) U2.58(VOUT) U2.59(VOUT) U2.60(VOUT) U2.68(VOUT) U11.1(VDD01) U11.6(VDD02) U11.10(VDD03) U12.1(VDD01) U12.6(VDD02) U12.10(VDD03) U13.1(VDD01) U13.6(VDD02) U13.10(VDD03) U14.1(VDD01) U14.6(VDD02) U14.10(VDD03) U15.1(VDD1) U15.19(VDD2) U15.20(VDD3) U15.38(VDD4) U16.1(VDD1) U16.19(VDD2) U16.20(VDD3) U16.38(VDD4) U22.24(V+) U23.14(3.3V_EXT) U24.16(VCC) U25.9(ISENSE2) U25.12(IN2) U27.4(VDD) ; also on sheet 1 8 9 10
3.3V_SL4_SHP: BD10.1 C227.2 M2.1(S1) M2.2(S2) M2.3(S3) R117.2 R119.1 U25.19(DISCH2) ; also on sheet 8
3VG: M2.4(G) R123.1 U25.2(GATE2)
3VS: R116.1 R117.1 U25.6(VSENSE2)
5VCC_EXT: C1.2 C2.2 C3.1 C4.2 C10.2 C11.2 C28.2 C29.1 C30.2 C31.2 P1.1(+12V) R12.1 U1.1(PVIN) U1.3(VIN) U1.11(PVIN) U1.12(PVIN) U1.39(PVIN) U1.40(PVIN) U3.1(PVIN) U3.3(VIN) U3.11(PVIN) U3.12(PVIN) U3.39(PVIN) U3.40(PVIN)
12V_SL4_SHP: BD9.2 C226.2 M1.1(S1) M1.2(S2) M1.3(S3) R114.1 R118.1 U25.20(DISCH1) ; also on sheet 8
12VCC_EXT: BD9.1 C8.2 C9.2 C12.2 C13.2 C14.2 C15.2 C16.2 C17.2 C19.2 C20.2 C21.2 C231.2 C232.2 M1.5(D1) M1.6(D2) M1.7(D3) M1.8(D4) P1.4(+5V) PWR1.1(GND) PWR1.2(GND) PWR1.3(GND) R11.1 R127.1 TP1.1 U2.2(VIN) U2.15(VIN) U2.42(PVIN) U2.43(PVIN) U2.44(PVIN) U2.66(PVIN) U2.69(PVIN) U25.10(ISENSE1) U25.11(IN1) ; also on sheet 8 9
12VG: M1.4(G) R125.1 U25.1(GATE1)
12VS: R114.2 R115.1 U25.7(VSENSE1)
GND: C1.1 C2.1 C3.2 C4.1 C5.1 C6.1 C7.2 C8.1 C9.1 C10.1 C11.1 C12.1 C13.1 C14.1 C15.1 C16.1 C17.1 C18.1 C19.1 C20.1 C21.1 C22.1 C23.1 C24.1 C25.1 C26.1 C27.2 C28.1 C29.2 C30.1 C31.1 C32.1 C33.1 C34.2 C35.1 C168.1 C169.1 C170.1 C171.1 C172.1 C173.1 C174.1 C175.1 C176.1 C177.1 C178.1 C179.1 C180.1 C181.1 C182.1 C183.1 C184.1 C185.1 C186.1 C187.1 C188.1 C189.1 C190.1 C191.1 C192.1 C193.1 C194.1 C195.1 C196.1 C197.1 C217.1 C218.1 C219.1 C220.1 C221.1 C222.1 C225.1 C226.1 C227.1 C228.1 C229.1 C230.1 C231.1 C232.1 C233.1 C234.1 C235.1 C236.1 C237.1 C238.1 C239.1 C240.1 C241.1 C242.1 C243.1 C244.1 C245.1 D1.1(C) D2.1(C) DS1.1(CATHODE) DS2.1(CATHODE) DS3.1(CATHODE) DS18.1(CATHODE) J5.4 J6.1 J10.1 P1.2(GND) P1.3(GND1) PWR1.4(GND) PWR1.5(12V) PWR1.6(12V) Q1.S Q2.S R2.1 R3.1 R4.1 R5.1 R7.1 R9.1 R21.1 R22.1 R23.1 R24.1 R102.2 R110.2 R115.2 R116.2 R124.2 R126.2 RD5.1 RD30.2 RD31.2 RD32.2 RD33.2 RD34.2 RD35.2 RD36.2 RD37.2 RD64.2 RD65.2 RD66.2 RD67.2 RD68.2 RD81.1 RD82.1 RP27.2 RP28.2 RP29.2 RP30.2 S1.3 S1.4 S2.3 S2.4 U1.2(AGND) U1.20(PGND) U1.21(PGND) U1.23(AGND) U1.31(PGND) U1.32(PGND) U1.33(PGND) U2.1(PGND) U2.5(PGND) U2.17(PGND) U2.33(PGND) U2.34(PGND) U2.37(PGND) U2.38(PGND) U2.39(PGND) U2.40(PGND) U2.41(PGND) U2.45(NC5) U2.46(PGND) U2.47(PGND) U2.48(PGND) U2.49(PGND) U2.50(PGND) U2.51(PGND) U2.62(PGND) U2.63(PGND) U2.64(PGND) U2.65(PGND) U2.67(PGND) U2.70(PGND) U2.72(PGND) U3.2(AGND) U3.20(PGND) U3.21(PGND) U3.23(AGND) U3.31(PGND) U3.32(PGND) U3.33(PGND) U11.5(GND01) U11.11(GND02) U11.20(GND03) U11.21(HEATGND) U12.5(GND01) U12.11(GND02) U12.20(GND03) U12.21(HEATGND) U13.5(GND01) U13.11(GND02) U13.20(GND03) U13.21(HEATGND) U14.5(GND01) U14.11(GND02) U14.20(GND03) U14.21(HEATGND) U15.18(GND1) U15.21(GND2) U15.39(GND3) U15.42(GND4) U15.43(HEATGND) U16.18(GND1) U16.21(GND2) U16.39(GND3) U16.42(GND4) U16.43(HEATGND) U21.1(GND) U22.12(GND) U23.7(GND) U24.8(GND) U24.10(C1) U24.13(D1) U24.14(D0) U24.15(\\E) U25.3(DGND) U25.8(AGND) U26.1(GND) U27.1(GND) ; also on sheet 1 7 8 9 10 12
ATNLED#_S: DS16.1(CATHODE) U22.5(IO01)
BUTTON#_S: C225.2 R112.2 R113.2 U22.18(IO13)
CKMODE: RD5.2 U6.E12(CKMODE)
CLKBUF_INPUT_SEL: RP87.1 U6.L3(CLKBUF_INPUT_SEL)
CLKBUF_OE_2_L: RP68.2 U26.4(A2)
CLKBUF_OE_3_L: RP91.2 U26.5(A3)
CLKBUF_OE_8_L: RP90.2 U26.6(A4)
CLKBUF_OE_PHY0: J6.3 RP71.2 U26.17(B2)
CLKBUF_OE_PHY1: J6.4 RP80.2 U26.16(B3)
CLKBUF_OE_SLOT4: J10.2 RP81.2 U26.15(B4)
CLKEN#_S: TP18.1 U22.7(IO03) U24.11(C0)
CLKEN_n_SL: R126.1 TP20.1 U24.9(YC)
CLKREQ_L_0: J6.2 RP70.2 U26.18(B1)
CLKREQ_L_4: J10.3 RP82.2 U26.14(B5)
CPERST_L: R135.2 RP75.2 U23.4(A) ; also on sheet 7
FAULT#: R130.2 R131.1 U25.16(~{FAULT})
GPIO_0: J11.1 U6.A13(GPIO_0/HP_LED_0)
GPIO_1: J11.3 U6.A12(GPIO_1/HP_LED_1)
GPIO_2: J11.5 U6.B14(GPIO_2/HP_LED_2)
GPIO_3: J11.7 U6.B13(GPIO_3/HP_LED_3)
GPIO_4: J11.9 U6.C14(GPIO_4/HP_LED_4)
GPIO_5: J11.11 U6.C12(GPIO_5/HP_LED_5)
GPIO_6: J11.13 U6.D14(GPIO_6/HP_LED_6)
GPIO_7: J11.15 RP65.2 U6.N2(GPIO_7/HP_LED_7) U26.10(A8)
GPIO_8: J11.17 RP69.2 U6.N3(GPIO_08/CLKREQ_0_L/HP_PWREN) U26.3(A1)
GPIO_9: J11.19 U6.N1(GPIO_09/CLKREQ_1_L/HP_CLKEN_L)
GPIO_10: J11.21 U6.M5(GPIO_10/CLKREQ_2_L/HP_PERST_L)
GPIO_11: J11.23 U6.M4(GPIO_11/CLKREQ_3_L/HP_PWRLED_L)
GPIO_12: J11.25 RP89.2 U6.M2(GPIO_12/CLKREQ_4_L/HP_ATNLED_L) U26.7(A5)
GPIO_13: J11.27 U6.M3(GPIO_13/CLKREQ_5_L/HP_INTERLOCK)
GPIO_14: J11.29 U6.M1(GPIO_14/CLKREQ_6_L/HP_MRL_L)
GPIO_15: J11.31 U6.L1(GPIO_15/CLKREQ_7_L/HP_BUTTON_L)
GPIO_16: J11.2 U6.K1(GPIO_16/HP_RST_0_L)
GPIO_17: J11.4 U6.K3(GPIO_17/HP_RST_1_L)
GPIO_18: J11.6 U6.K2(GPIO_18/HP_RST_2_L)
GPIO_19: J11.8 U6.K4(GPIO_19/HP_RST_3_L)
GPIO_20: J11.10 U6.J2(GPIO_20/HP_RST_4_L)
GPIO_21: J11.12 U6.J3(GPIO_21/HP_RST_5_L)
GPIO_22: J11.14 U6.J1(GPIO_22/HP_RST_6_L)
GPIO_23: J11.16 RP67.2 U6.H1(GPIO_23/HP_RST_7_L) U26.8(A6)
GPIO_24: J11.18 U6.H3(GPIO_24/HP_PWRFLT_L)
GPIO_25: J11.20 U6.G1(GPIO_25/HP_PWR_GOOD)
GPIO_26: J11.22 U6.G2(GPIO_26/CKBUFPD_L) ; also on sheet 10
GPIO_27: J11.24 U6.G3(GPIO_27/MPHP_PS_0)
GPIO_28: J11.26 U6.F3(GPIO_28/MPHP_PS_1)
GPIO_29: J11.28 U6.F4(GPIO_29/MPHP_PS_2)
GPIO_30: J11.30 U6.E4(GPIO_30/PHY_SRAM_BYPASS) ; also on sheet 10
GPIO_31: J11.32 U6.E3(GPIO_31/SUPPRISE_HP) ; also on sheet 10
GPIO_S: TP19.1 U22.10(IO06)
HP_LED_7: R134.1 RP74.2 U26.11(B8)
HP_RST_7_L: RP72.2 U26.13(B6) ; also on sheet 8
HPSCL: J5.2 R108.1 U21.6(SCL2) U22.22(SCL)
HPSDA: J5.3 R109.1 U21.5(SDA2) U22.23(SDA)
INTERLOCK_S: DS17.2(ANODE) U22.9(IO05)
IOE_ADDR0: RD64.1 RP60.2 U22.21(A0)
IOE_ADDR1: RD65.1 RP61.2 U22.2(A1)
IOE_ADDR2: RD66.1 RP62.2 U22.3(A2)
IS1: R127.2 U25.15(ISET1)
IS2: R128.2 U25.14(ISET2)
Ln1_SEL: RP31.2 SW5.1(A1) U11.9(SEL)
Ln2_SEL: RP32.2 SW5.2(A2) U12.9(SEL)
Ln3_SEL1: RP33.2 SW5.3(A3) U15.41(SEL1)
Ln3_SEL2: RP34.2 SW5.4(A4) U15.40(SEL2)
Ln5_SEL: RP35.2 SW6.1(A1) U13.9(SEL)
Ln6_SEL: RP36.2 SW6.2(A2) U14.9(SEL)
Ln7_SEL1: RP37.2 SW6.3(A3) U16.41(SEL1)
Ln7_SEL2: RP38.2 SW6.4(A4) U16.40(SEL2)
MR#: R135.1 S2.1 S2.2 U27.3(MR#)
MRESET_L: RP76.2 U23.5(B) U27.2(RESET#)
MRL#_S: RP63.2 SW14.8(B1) U22.17(IO12) U23.3(Y)
PDC_L_7: RP66.2 U26.9(A7) ; also on sheet 10
PERn1_RECEPT: U11.3(A0+) ; also on sheet 11
PERn2_RECEPT: U12.3(A0+) ; also on sheet 11
PERn3_RECEPT: U15.3(A0-) ; also on sheet 11
PERn5_RECEPT: U13.4(A0-) ; also on sheet 11
PERn6_RECEPT: U14.4(A0-) ; also on sheet 11
PERn7_RECEPT: U16.15(A3-) ; also on sheet 11
PERp1_RECEPT: U11.4(A0-) ; also on sheet 11
PERp2_RECEPT: U12.4(A0-) ; also on sheet 11
PERp3_RECEPT: U15.2(A0+) ; also on sheet 11
PERp5_RECEPT: U13.3(A0+) ; also on sheet 11
PERp6_RECEPT: U14.3(A0+) ; also on sheet 11
PERp7_RECEPT: U16.14(A3+) ; also on sheet 11
PERST4_L: R120.1 R153.2
PERST#_S: U22.8(IO04) U24.5(B0)
PERST#_SL1: R145.2 ; also on sheet 9
PERST#_SL2: R146.2 ; also on sheet 9
PERST#_SL3: R147.2 ; also on sheet 9
PERST#_SL4: R122.1 U24.7(YB) ; also on sheet 8
PERST#_SL5: R154.2 ; also on sheet 8
PERST#_SL6: R155.2 ; also on sheet 8
PERST#_SL7: R156.2 ; also on sheet 8
PERST_L: R139.1 U23.6(Y) U23.10(B) U23.13(B) ; also on sheet 10
PERST_L_3V3: R139.2 ; also on sheet 10
PETn1_RECEPT: U11.7(A1+) ; also on sheet 11
PETn2_RECEPT: U12.7(A1+) ; also on sheet 11
PETn3_RECEPT: U15.15(A3-) ; also on sheet 11
PETn5_RECEPT: U13.8(A1-) ; also on sheet 11
PETn6_RECEPT: U14.8(A1-) ; also on sheet 11
PETn7_RECEPT: U16.3(A0-) ; also on sheet 11
PETp1_RECEPT: U11.8(A1-) ; also on sheet 11
PETp2_RECEPT: U12.8(A1-) ; also on sheet 11
PETp3_RECEPT: U15.14(A3+) ; also on sheet 11
PETp5_RECEPT: U13.7(A1+) ; also on sheet 11
PETp6_RECEPT: U14.7(A1+) ; also on sheet 11
PETp7_RECEPT: U16.2(A0+) ; also on sheet 11
PIN6_DWNRST_L: R144.2 R145.1 R146.1 R147.1 U23.8(Y)
PIN8_DWNRST_L: R152.2 R153.1 R154.1 R155.1 R156.1 U23.11(Y)
PRSNT#_SL4: U22.16(IO11) U23.2(B) ; also on sheet 8
PRSNT#_SL7: RP73.2 U26.12(B7) ; also on sheet 8
PWR_OCP_U2: R2.2 TP5.1 U1.4(OCP_SEL)
PWR_OCP_U3: R21.2 TP12.1 U3.4(OCP_SEL)
PWR_SS_U2: C18.2 U1.28(SS/TR)
PWR_SS_U3: C35.2 U3.28(SS/TR)
PWR_STSEL_U2: R3.2 U1.29(STSEL)
PWR_STSEL_U3: R22.2 U3.29(STSEL)
PWREN_S: U22.6(IO02) U24.2(A0)
PWREN_SL: R124.1 U24.4(YA) U25.18(ENABLE)
PWRFLT#_S: R131.2 U22.19(IO14)
PWRGOOD_S: R129.2 U22.20(IO15) U25.13(PWRGD2) U25.17(PWRGD1)
PWRLED#_S: DS15.1(CATHODE) U22.4(IO00)
REFCLKIN_R: U6.A3(REFCLKIN) ; also on sheet 7
REFCLKIP_R: U6.A4(REFCLKIP) ; also on sheet 7
REFCLKN_SL1: R99.2 ; also on sheet 9
REFCLKN_SL2: R97.2 ; also on sheet 9
REFCLKN_SL3: R95.2 ; also on sheet 9
REFCLKN_SL4: R160.2 ; also on sheet 8
REFCLKN_SL5: R93.2 ; also on sheet 8
REFCLKN_SL6: R91.2 ; also on sheet 8
REFCLKN_SL7: R88.2 ; also on sheet 8
REFCLKON0: R158.1 U6.A1(REFCLKON0)
REFCLKON1: R99.1 U6.B3(REFCLKON1)
REFCLKON2: R97.1 U6.C4(REFCLKON2)
REFCLKON3: R95.1 U6.C2(REFCLKON3)
REFCLKON4: R160.1 U6.C1(REFCLKON4)
REFCLKON5: R93.1 U6.D2(REFCLKON5)
REFCLKON6: R91.1 U6.E1(REFCLKON6)
REFCLKON7: R88.1 U6.F1(REFCLKON7)
REFCLKON_PHY0: R158.2 U6.A8(REFCLKN0)
REFCLKON_PHY1: RD82.2 U6.P8(REFCLKN1)
REFCLKOP0: R157.1 U6.A2(REFCLKOP0)
REFCLKOP1: R98.1 U6.B4(REFCLKOP1)
REFCLKOP2: R96.1 U6.C5(REFCLKOP2)
REFCLKOP3: R94.1 U6.C3(REFCLKOP3)
REFCLKOP4: R159.1 U6.B1(REFCLKOP4)
REFCLKOP5: R92.1 U6.D3(REFCLKOP5)
REFCLKOP6: R90.1 U6.D1(REFCLKOP6)
REFCLKOP7: R89.1 U6.F2(REFCLKOP7)
REFCLKOP_PHY0: R157.2 U6.B8(REFCLKP0)
REFCLKOP_PHY1: RD81.2 U6.N8(REFCLKP1)
REFCLKP_SL1: R98.2 ; also on sheet 9
REFCLKP_SL2: R96.2 ; also on sheet 9
REFCLKP_SL3: R94.2 ; also on sheet 9
REFCLKP_SL4: R159.2 ; also on sheet 8
REFCLKP_SL5: R92.2 ; also on sheet 8
REFCLKP_SL6: R90.2 ; also on sheet 8
REFCLKP_SL7: R89.2 ; also on sheet 8
RESREF: R102.1 U6.E8(RESREF)
RXn1_SL1: U11.15(C0+) ; also on sheet 9
RXn1_UP: U11.19(B0+) ; also on sheet 7
RXn2_SL2: U12.15(C0+) ; also on sheet 9
RXn2_UP: U12.19(B0+) ; also on sheet 7
RXn3_SL2: U15.36(B0-) ; also on sheet 9
RXn3_SL3: U15.34(C0-) ; also on sheet 9
RXn3_UP: U15.5(D0-) ; also on sheet 7
RXn5_SL4: U13.14(C0-) ; also on sheet 8
RXn5_SL5: U13.18(B0-) ; also on sheet 8
RXn6_SL4: U14.14(C0-) ; also on sheet 8
RXn6_SL6: U14.18(B0-) ; also on sheet 8
RXn7_SL4: U16.17(D3-) ; also on sheet 8
RXn7_SL6: U16.22(C3-) ; also on sheet 8
RXn7_SL7: U16.24(B3-) ; also on sheet 8
RXp1_SL1: U11.14(C0-) ; also on sheet 9
RXp1_UP: U11.18(B0-) ; also on sheet 7
RXp2_SL2: U12.14(C0-) ; also on sheet 9
RXp2_UP: U12.18(B0-) ; also on sheet 7
RXp3_SL2: U15.37(B0+) ; also on sheet 9
RXp3_SL3: U15.35(C0+) ; also on sheet 9
RXp3_UP: U15.4(D0+) ; also on sheet 7
RXp5_SL4: U13.15(C0+) ; also on sheet 8
RXp5_SL5: U13.19(B0+) ; also on sheet 8
RXp6_SL4: U14.15(C0+) ; also on sheet 8
RXp6_SL6: U14.19(B0+) ; also on sheet 8
RXp7_SL4: U16.16(D3+) ; also on sheet 8
RXp7_SL6: U16.23(C3+) ; also on sheet 8
RXp7_SL7: U16.25(B3+) ; also on sheet 8
SHCL_I2C: R105.1 U21.3(SCL1) ; also on sheet 10
SHDA_I2C: R106.1 U21.4(SDA1) ; also on sheet 10
SHP_HP_CTRL: RP64.2 SW14.7(B2) U24.1(S)
SHPINT: J5.1 U22.1(~{INT}) ; also on sheet 10
SL7: DS18.2(ANODE) R134.2
TXn1_SL1: U11.13(C1+) ; also on sheet 9
TXn1_UP: U11.17(B1+) ; also on sheet 7
TXn2_SL2: U12.13(C1+) ; also on sheet 9
TXn2_UP: U12.17(B1+) ; also on sheet 7
TXn3_SL2: U15.24(B3-) ; also on sheet 9
TXn3_SL3: U15.22(C3-) ; also on sheet 9
TXn3_UP: U15.17(D3-) ; also on sheet 7
TXn5_SL4: U13.12(C1-) ; also on sheet 8
TXn5_SL5: U13.16(B1-) ; also on sheet 8
TXn6_SL4: U14.12(C1-) ; also on sheet 8
TXn6_SL6: U14.16(B1-) ; also on sheet 8
TXn7_SL4: U16.5(D0-) ; also on sheet 8
TXn7_SL6: U16.34(C0-) ; also on sheet 8
TXn7_SL7: U16.36(B0-) ; also on sheet 8
TXp1_SL1: U11.12(C1-) ; also on sheet 9
TXp1_UP: U11.16(B1-) ; also on sheet 7
TXp2_SL2: U12.12(C1-) ; also on sheet 9
TXp2_UP: U12.16(B1-) ; also on sheet 7
TXp3_SL2: U15.25(B3+) ; also on sheet 9
TXp3_SL3: U15.23(C3+) ; also on sheet 9
TXp3_UP: U15.16(D3+) ; also on sheet 7
TXp5_SL4: U13.13(C1+) ; also on sheet 8
TXp5_SL5: U13.17(B1+) ; also on sheet 8
TXp6_SL4: U14.13(C1+) ; also on sheet 8
TXp6_SL6: U14.17(B1+) ; also on sheet 8
TXp7_SL4: U16.4(D0+) ; also on sheet 8
TXp7_SL6: U16.35(C0+) ; also on sheet 8
TXp7_SL7: U16.37(B0+) ; also on sheet 8
U1_PGOOD: R6.1 TP9.1 U2.19(PWRGD)
U1_PH1: U2.11(PH1) U2.22(PH2) U2.23(PH3) U2.24(PH4) U2.25(PH5) U2.26(PH6) U2.27(PH7) U2.28(PH8) U2.71(PH9)
U1_V5V: R8.1 R10.1 U2.61(V5V)
U2_PGOOD: Q1.G R1.2 R16.2
U2_PH1: U1.10(PH1) U1.13(PH2) U1.14(PH3) U1.15(PH4) U1.16(PH5) U1.17(PH6) U1.18(PH7) U1.19(PH8) U1.42(PH9)
U3_PGOOD: Q2.G R18.2 R20.2
U3_PH1: U3.10(PH1) U3.13(PH2) U3.14(PH3) U3.15(PH4) U3.16(PH5) U3.17(PH6) U3.18(PH7) U3.19(PH8) U3.42(PH9)
U9_OE: R133.2 ; also on sheet 10
N19466357: DS4.2(ANODE) R17.2
N19466360: DS4.1(CATHODE) Q1.D
N19467283: DS5.2(ANODE) R19.2
N19467285: DS5.1(CATHODE) Q2.D
N20181756: R148.2 U23.12(A)
N20182455: R143.2 U23.9(A)
N20286958: RD31.1 SW5.7(B2)
N20286960: RD32.1 SW5.6(B3)
N20286962: RD33.1 SW5.5(B4)
N20286980: RD30.1 SW5.8(B1)
N22226783: R121.2 U24.3(A1)
N22226854: C235.2 U25.5(VREG)
N22226894: C236.2 U25.4(TIMER)
N22226919: C229.2 R123.2
N22226922: C228.2 R125.2
N22226992: R120.2 R122.2 U24.6(B1)
N22227000: DS17.1(CATHODE) R110.1
N22227049: D2.2(A) R118.2
N22227050: D1.2(A) R119.2
N22227069: R111.2 U23.1(A)
N22818950: C222.2 R107.1 U21.7(VREF2) U21.8(EN)
N22828371: R113.1 S1.1 S1.2
N24248530: TP8.1 U2.16(INH)
N24248584: R6.2 R7.2 U2.3(SS_SEL)
N24248628: R8.2 R9.2 U2.7(FREQ_SEL)
N24248658: R10.2 U2.18(PWRGD_PU)
N24248709: R14.2 U2.13(VADJ)
N24248723: R14.1 U2.9(AGND)
N27647127: RP28.1 U11.2(PD)
N27649684: RP29.1 U12.2(PD)
N27652062: RP30.1 U14.2(PD)
N27652214: RP27.1 U13.2(PD)
N27804735: C238.2 R132.1 R133.1 U26.19(VREFB) U26.20(EN)
N27826396: RD34.1 SW6.8(B1)
N27826398: RD35.1 SW6.7(B2)
N27826400: RD37.1 SW6.5(B4)
N27826402: RD36.1 SW6.6(B3)
N27963842: RD68.1 SW14.2(A2)
N27963843: RD67.1 SW14.1(A1)
N27963844: DS16.2(ANODE) R104.2
N27963846: DS15.2(ANODE) R103.2
N28028821: R5.2 U1.22(RT/CLK)
N28030818: R4.2 U1.26(VADJ)
N28036168: R1.1 U1.8(PWRGD)
N28067181: R24.2 U3.22(RT/CLK)
N28067218: R23.2 U3.26(VADJ)
N28067330: R20.1 U3.8(PWRGD)
N28402598: DS3.2(ANODE) R12.2
N28402599: TP2.1 U1.7(SYNC_OUT)
N28402600: TP10.1 U3.7(SYNC_OUT)
N28402601: TP3.1 U1.30(INH/UVLO)
N28402602: TP11.1 U3.30(INH/UVLO)
N28402603: DS1.2(ANODE) R11.2
N28402604: TP13.1 U3.6(ILIM)
N28402605: DS2.2(ANODE) R13.2
N28402606: TP6.1 U1.6(ILIM)

Not connected (* = marked no-connect by the designer): SW14 3(A3)* 4(A4)* 5(B4)* 6(B3)*; U1 5(DNC1)* 9(DNC2)* 24(DNC3)* 25(ISHARE)*; U2 4(DNC1)* 6(ILIM)* 8(DNC2)* 12(DNC3)* 20(DNC4)* 21(DNC5)* 29(NC1)* 30(NC2)* 31(NC3)* 32(NC4)* 35(DNC6)* 36(DNC7)*; U3 5(DNC1)* 9(DNC2)* 24(DNC3)* 25(ISHARE)*; U15 6(A1+)* 7(A1-)* 8(D1+)* 9(D1-)* 10(A2+)* 11(A2-)* 12(D2+)* 13(D2-)* 26(C2-)* 27(C2+)* 28(B2-)* 29(B2+)* 30(C1-)* 31(C1+)* 32(B1-)* 33(B1+)*; U16 6(A1+)* 7(A1-)* 8(D1+)* 9(D1-)* 10(A2+)* 11(A2-)* 12(D2+)* 13(D2-)* 26(C2-)* 27(C2+)* 28(B2-)* 29(B2+)* 30(C1-)* 31(C1+)* 32(B1-)* 33(B1+)*; U22 11(IO07)* 13(IO08)* 14(IO09)* 15(IO10)*; U24 12(YD)*

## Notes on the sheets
sheet 13
- Lane 1
- Lane 2
- Lane 5
- Lane 6
- B. Set Signal Switch for different modes
- PI3PCIE3413AZHE Truth Table
- default
  setting
- PI3PCIE3212ZBEX Truth Table
- Default = 808
- 1
- 1
- Function
- SEL
- Function
- SEL1
- SEL2
- 0
- 1
- Lane
- MODE
- 208
- 308
- 408
- 508
- 808
- A to B
- L
- H
- 1
- Ln1_SEL
- L
- L
- L
- L
- H
- A to B
- L
- 0
- 0
- A to C
- H
- L
- 0
- 2
- Ln2_SEL
- L
- L
- H
- L
- H
- A to C
- H
- 1
- A to D
- H
- H
- Ln3_SEL1
- H
- H
- L
- H
- H
- 3
- Ln3_SEL2
- H
- H
- H
- H
- L
- 5
- Ln5_SEL
- H
- H
- H
- L
- L
- 6
- Ln6_SEL
- H
- L
- L
- L
- L
- Ln7_SEL1
- H
- H
- H
- L
- L
- 7
- Ln7_SEL2
- H
- L
- L
- H
- H
- Lane 3
- Lane 7
sheet 14
- 1. If the reference clock input is HCSL type, it can be DC coupling.
  2. If the 100MHz clock source is not in HCSL protocol (ex: LVPECL, LVDS , etc),
     Please refer to application note to add application circuit.
- CKMODE
- Mode
- 0
- Base (Default)
- 1
- CDSR
- When CKMODE is 0, all 8 lanes (0 ~7) of SERDES are driven by one reference clock source.
  When CKMODE is 1, 8 lanes of SERDES are driven by two separate reference clock source via two pairs of reference clock inputs.
sheet 15
- DWNRSTSEL
- DWNRSTSEL
sheet 17
- REVISION HISTORY OF PI7C9X3G808GP reference circuit
- REV
- DATE
- DESCRIPTION
- PAGE
- EDITOR
- 1.0
- 20_06_02
- New design version
- All
- Eros
- 1. U6.J4 pin name change to TEST
  2. Add pull low resistor RD85 at U6.J4
- 1.1
- 20_06_22
- 10
- Eros
- 1.2
- 20_07_13
- 1-1. R4 value change from 2.4K to 2.45K
- 1. 0.9V change to 0.95V
- 06
- Eros
- 1-2. R23 value change from 2.4K to 2.45K
- 1-3 Power source change text from
  0.9V to 0.95V
- 13
- 1.3
- 20_09_02
- 1. C215 & C216 change part to R183 & R184
  2. Add note for REFCLKIP/N input
- 15
- Eros
- 1. Remove Debug circuit
  2. CHIPMODE fix to 00b (Normal Mode)
  3. CKMODE fix to 0, REFCLKP/N_1 connect
  to GND via 330R
  4. Remove external clock buffer part.
  5. SSC Isolation function / circuit
  removed
- 1.4
- 21_01_20
- All
- Eros
- 1.5
- 21_02_09
- 1. Change pin name from HP_PDC_L_[x] to
  PDC_L_[x]
- 11, 16
- 9,10
- Eros
- 1. Change CLKBUFPD_L pin
  default settiing value from 0 to 1
- 11
- Eros
- 1.6
- 21_07_07
- 11_History
sheet 19
- SERIAL HOT PLUG (P4)
- SHP I2C Level Shift
- Serial Hot Plug Port / IOE_ADDR[2:0] Mapping
- SHP Port
- IOE_ADDR[2:0]
- 1
- 000
- 2
- 001
- SHP Port  (PORT4)
- 3
- 010
- 1
- 1
- 0
- 4
- 011
- 5
- 100
- 6
- 101
- 7
- 110
- If use SHP function
  R122 need to remove
- default
  setting
- 0
- 1
- #E
- S
- YA
- YB
- YC
- YD
- Function
- H
- X
- Hi-Z
- Hi-Z
- Hi-Z
- Hi-Z
- Disable
- L
- L
- A0
- B0
- C0
- D0
- S = 0
- L
- H
- A1
- B1
- C1
- D1
- S = 1
- Partial PHP (P7) / PM L1.1 ( P0 / P4)
- HOT_PLUG_EN_[L]
- SURPRISE_HP_EN
- PM_L11_EN_[L]
- Functional Mode
- 0
- 1
- 1
- Partial PHP
- 0
- 0
- 1
- Serial Hot Plug
- 1
- 1
- 0
- PM L1.1
- SLOT7
- Port 7
sheet 20
- ATX POWER
  CONNECTOR
- Rset
- R(RT)
- Overcurrent Protection SELECT
  OPEN = Hiccup Mode (Default)
  CONNECT TO AGND = Cycle-by-cycle Mode
- (3.3V / 20A)
- Slow-Start Capacitor Valueand Slow-Start Time
- Css (nF)
- OPEN
- 3.3
- 4.7
- 10
- 15
- 22
- 33
- SS Time (msec)
- 1.2
- 2.1
- 2.5
- 3.8
- 5.1
- 7.0
- 9.8
- Power module Setting: (Vin=5V)
  Vout = [ ( 1.43 / Rset ) + 1 ] x 0.6
  Vout   Rset    R(RT)   fsw
  0.95V  2.45K   1M      250KHz
- Pin 45 (NC) is connected to PGND to
  improve the routing of the PCB layout
- Power module Setting: (Vin=12V)
  Vout  Rset
  3.30V 326ohm
- 0.9V_VDDC indicator
- 0.9V_VP indicator
- Rset
- R(RT)
- Overcurrent Protection SELECT
  OPEN = Hiccup Mode (Default)
  CONNECT TO AGND = Cycle-by-cycle Mode
- Slow-Start Capacitor Valueand Slow-Start Time
- Css (nF)
- OPEN
- 3.3
- 4.7
- 10
- 15
- 22
- 33
- SS Time (msec)
- 1.2
- 2.1
- 2.5
- 3.8
- 5.1
- 7.0
- 9.8
- Power module Setting: (Vin=5V)
  Vout = [ ( 1.43 / Rset ) + 1 ] x 0.6
  Vout   Rset    R(RT)   fsw
  0.95V  2.45K   1M      250KHz
